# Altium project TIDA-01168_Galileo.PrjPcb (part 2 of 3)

## Sheet TIDA-01168_Control.SchDoc: System Control
size 431 x 279 mm; Date: Not shown in title block; ApprovedBy: Not shown in title block; CheckedBy: Not shown in title block; Author: Not shown in title block; CompanyName: Not shown in title block; Engineer: Not shown in title block; Organization: Not shown in title block; Address1: Not shown in title block; Address2: Not shown in title block; Address3: Not shown in title block; Address4: Not shown in title block; DocumentNumber: 8; Revision: Use project parameter SCH_Rev; SheetNumber: 8; SheetTotal: 11; PageSetup: Record=PageOptions¦CenterHorizontal=True¦CenterVertical=True¦PrintScale=1.00¦XCorrection=1.00¦YCorrection=1.00¦PrintKind=0¦BorderSize=5000000¦LeftOffset=0¦BottomOffset=0¦Orientation=2¦PaperLength=1000¦PaperWidth=1000¦Scale=100¦PaperSource=15¦PrintQuality=600¦MediaType=1¦DitherType=10¦PaperKind=Letter¦PrintScaleMode=1
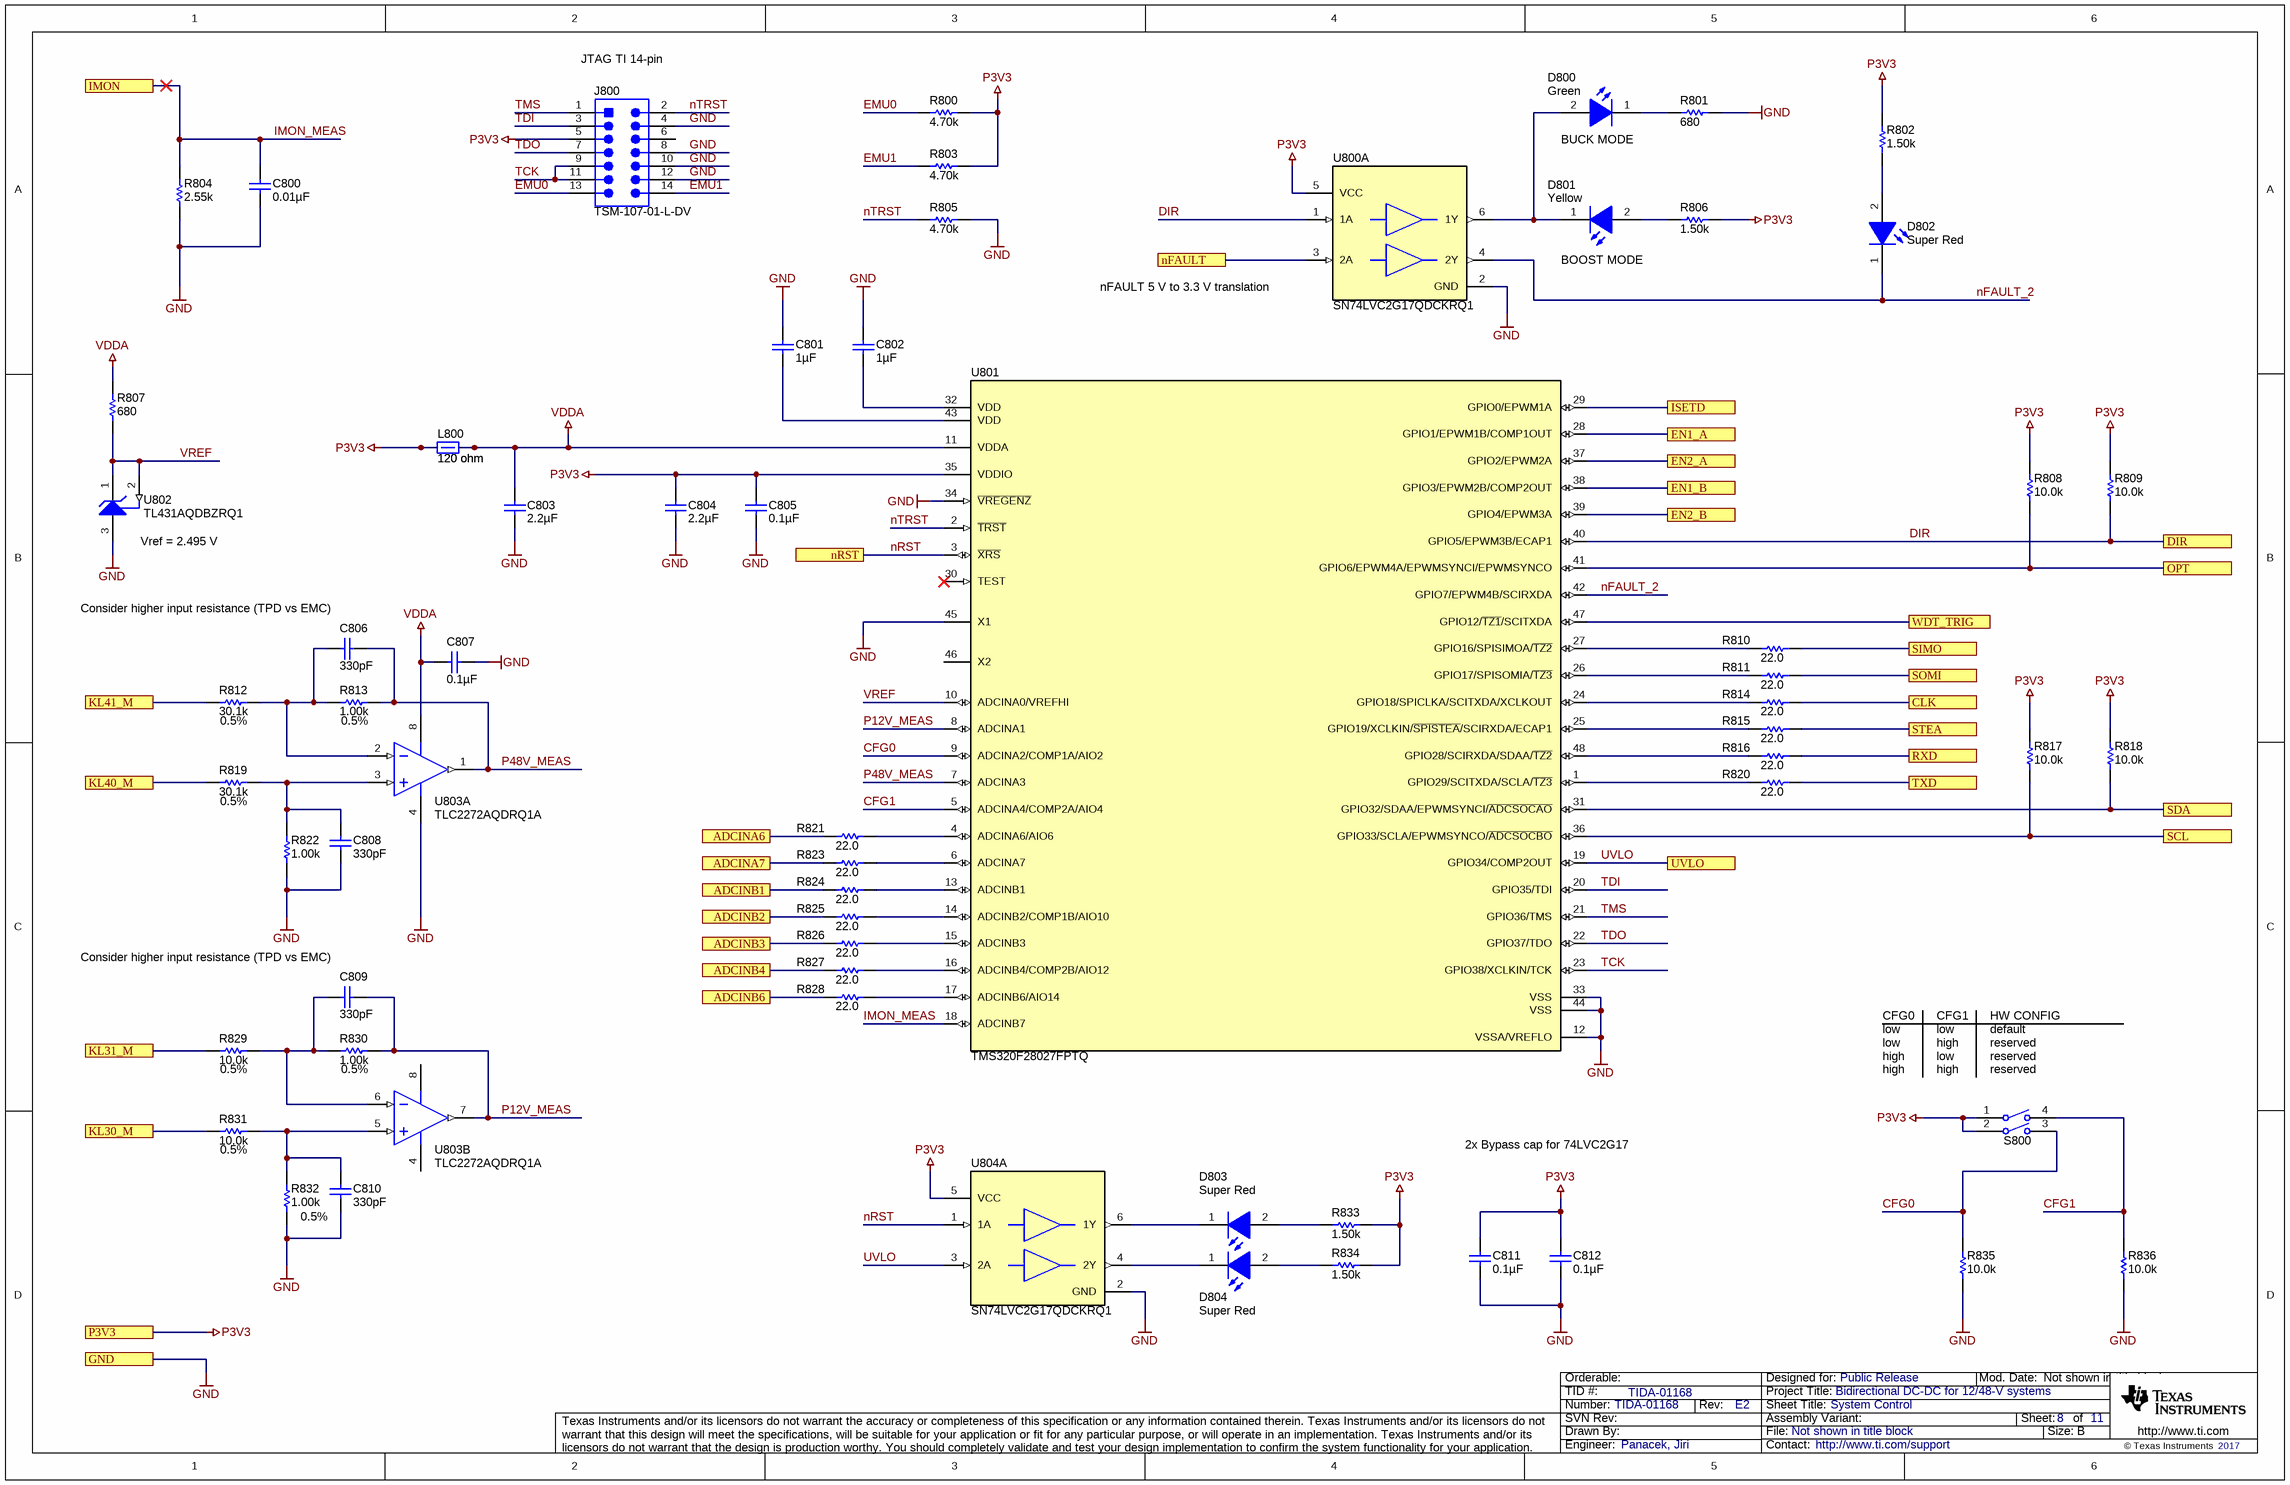
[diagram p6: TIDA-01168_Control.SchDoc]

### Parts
C800  ValueDisplayed: 0.01µF  [0603]  (hidden comment: GCM188R71H103KA37D)
C801  ValueDisplayed: 1µF  [0603]  (hidden comment: GCM188R71E105KA64D)
C802  ValueDisplayed: 1µF  [0603]  (hidden comment: GCM188R71E105KA64D)
C803  ValueDisplayed: 2.2µF  [0603]  (hidden comment: GCM188R70J225KE22D)
C804  ValueDisplayed: 2.2µF  [0603]  (hidden comment: GCM188R70J225KE22D)
C805  ValueDisplayed: 0.1µF  [0603]  (hidden comment: GCM188R71H104KA57D)
C806  ValueDisplayed: 330pF  [0603]  (hidden comment: C1608C0G2A331J080AA)
C807  ValueDisplayed: 0.1µF  [0603]  (hidden comment: GCM188R71H104KA57D)
C808  ValueDisplayed: 330pF  [0603]  (hidden comment: C1608C0G2A331J080AA)
C809  ValueDisplayed: 330pF  [0603]  (hidden comment: C1608C0G2A331J080AA)
C810  ValueDisplayed: 330pF  [0603]  (hidden comment: C1608C0G2A331J080AA)
C811  ValueDisplayed: 0.1µF  [0603]  (hidden comment: GCM188R71H104KA57D)
C812  ValueDisplayed: 0.1µF  [0603]  (hidden comment: GCM188R71H104KA57D)
D800  value Green  [WL-SMCW_GREEN]  (hidden comment: 150060GS75000)
D801  value Yellow  [WL-SMCW_YELLOW]  (hidden comment: 150060YS75000)
D802  value Super Red  [WL-SMCW_RED]  (hidden comment: 150060SS75000)
D803  value Super Red  [WL-SMCW_RED]  (hidden comment: 150060SS75000)
D804  value Super Red  [WL-SMCW_RED]  (hidden comment: 150060SS75000)
J800  TSM-107-01-L-DV  [Samtec_TSM-107-01-x-DV]
L800  value 120 ohm  [0603]  (hidden comment: BLM18AG121SN1D)
R800  ValueDisplayed: 4.70k  [0603]  (hidden comment: RC0603FR-074K7L)
R801  ValueDisplayed: 680  [0603]  (hidden comment: RC0603FR-07680RL)
R802  ValueDisplayed: 1.50k  [0603]  (hidden comment: RC0603FR-071K5L)
R803  ValueDisplayed: 4.70k  [0603]  (hidden comment: RC0603FR-074K7L)
R804  ValueDisplayed: 2.55k  [0603]  (hidden comment: RC0603FR-072K55L)
R805  ValueDisplayed: 4.70k  [0603]  (hidden comment: RC0603FR-074K7L)
R806  ValueDisplayed: 1.50k  [0603]  (hidden comment: RC0603FR-071K5L)
R807  ValueDisplayed: 680  [0603]  (hidden comment: RC0603FR-07680RL)
R808  ValueDisplayed: 10.0k  [0603]  (hidden comment: RC0603FR-0710KL)
R809  ValueDisplayed: 10.0k  [0603]  (hidden comment: RC0603FR-0710KL)
R810  ValueDisplayed: 22.0  [0603]  (hidden comment: RC0603FR-0722RL)
R811  ValueDisplayed: 22.0  [0603]  (hidden comment: RC0603FR-0722RL)
R812  ValueDisplayed: 30.1k  Value1: 0.5%  [0603]  (hidden comment: RT0603DRE0730K1L)
R813  ValueDisplayed: 1.00k  Value1: 0.5%  [0603]  (hidden comment: RT0603DRE071KL)
R814  ValueDisplayed: 22.0  [0603]  (hidden comment: RC0603FR-0722RL)
R815  ValueDisplayed: 22.0  [0603]  (hidden comment: RC0603FR-0722RL)
R816  ValueDisplayed: 22.0  [0603]  (hidden comment: RC0603FR-0722RL)
R817  ValueDisplayed: 10.0k  [0603]  (hidden comment: RC0603FR-0710KL)
R818  ValueDisplayed: 10.0k  [0603]  (hidden comment: RC0603FR-0710KL)
R819  ValueDisplayed: 30.1k  Value1: 0.5%  [0603]  (hidden comment: RT0603DRE0730K1L)
R820  ValueDisplayed: 22.0  [0603]  (hidden comment: RC0603FR-0722RL)
R821  ValueDisplayed: 22.0  [0603]  (hidden comment: RC0603FR-0722RL)
R822  ValueDisplayed: 1.00k  [0603]  (hidden comment: RT0603DRE071KL)
R823  ValueDisplayed: 22.0  [0603]  (hidden comment: RC0603FR-0722RL)
R824  ValueDisplayed: 22.0  [0603]  (hidden comment: RC0603FR-0722RL)
R825  ValueDisplayed: 22.0  [0603]  (hidden comment: RC0603FR-0722RL)
R826  ValueDisplayed: 22.0  [0603]  (hidden comment: RC0603FR-0722RL)
R827  ValueDisplayed: 22.0  [0603]  (hidden comment: RC0603FR-0722RL)
R828  ValueDisplayed: 22.0  [0603]  (hidden comment: RC0603FR-0722RL)
R829  ValueDisplayed: 10.0k  Value1: 0.5%  [0603]  (hidden comment: RT0603DRE0710KL)
R830  ValueDisplayed: 1.00k  Value1: 0.5%  [0603]  (hidden comment: RT0603DRE071KL)
R831  ValueDisplayed: 10.0k  Value1: 0.5%  [0603]  (hidden comment: RT0603DRE0710KL)
R832  ValueDisplayed: 1.00k  Value1: 0.5%  [0603]  (hidden comment: RT0603DRE071KL)
R833  ValueDisplayed: 1.50k  [0603]  (hidden comment: RC0603FR-071K5L)
R834  ValueDisplayed: 1.50k  [0603]  (hidden comment: RC0603FR-071K5L)
R835  ValueDisplayed: 10.0k  [0603]  (hidden comment: RC0603FR-0710KL)
R836  ValueDisplayed: 10.0k  [0603]  (hidden comment: RC0603FR-0710KL)
S800  218-2LPST  [SW_218-2LP]  (value not drawn)
U800  SN74LVC2G17QDCKRQ1  [DCK0006A_N]  (part A of 2)
U801  TMS320F28027FPTQ  [PT0048A_N]
U802  TL431AQDBZRQ1  [DBZ0003A_N]
U803  TLC2272AQDRQ1A  [D0008A_N]  (parts A,B of 2)
U804  SN74LVC2G17QDCKRQ1  [DCK0006A_N]  (part A of 2)

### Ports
ADCINA6, ADCINA7, ADCINB1, ADCINB2, ADCINB3, ADCINB4, ADCINB6, CLK, DIR, EN1_A, EN1_B, EN2_A, EN2_B, GND, IMON, ISETD, KL30_M, KL31_M, KL40_M, KL41_M, nFAULT, nRST, OPT, P3V3, RXD, SCL, SDA, SIMO, SOMI, STEA, TXD, UVLO, WDT_TRIG

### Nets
GND: C800.2 C801.2 C802.2 C803.1 C804.1 C805.1 C807.2 C808.2 C810.2 C811.2 C812.2 J800.4 J800.8 J800.10 J800.12 R801.2 R804.1 R805.1 R822.2 R832.2 R835.1 R836.1 U800.2(GND) U801.12(VSSA/VREFLO) U801.33(VSS) U801.34(~{VREGENZ}) U801.44(VSS) U801.45(X1) U802.3(ANODE) U803.4(VDD-/GND) U804.2(GND) ; port GND
P3V3: C804.2 C805.2 C811.1 C812.1 J800.5 L800.1 R800.1 R802.2 R803.1 R806.2 R808.2 R809.2 R817.2 R818.2 R833.2 R834.2 S800.1 S800.2 U800.5(VCC) U801.35(VDDIO) U804.5(VCC) ; port P3V3
VDDA: C803.2 C807.1 L800.2 R807.1 U801.11(VDDA) U803.8(VDD+)
ADCINA6: R821.2 ; port ADCINA6
ADCINA7: R823.2 ; port ADCINA7
ADCINB1: R824.2 ; port ADCINB1
ADCINB2: R825.2 ; port ADCINB2
ADCINB3: R826.2 ; port ADCINB3
ADCINB4: R827.2 ; port ADCINB4
ADCINB6: R828.2 ; port ADCINB6
CFG0: R835.2 S800.3 U801.9(ADCINA2/COMP1A/AIO2)
CFG1: R836.2 S800.4 U801.5(ADCINA4/COMP2A/AIO4)
CLK: R814.1 ; port CLK
DIR: R809.1 U800.1(1A) U801.40(GPIO5/EPWM3B/ECAP1) ; port DIR
EMU0: J800.13 R800.2
EMU1: J800.14 R803.2
EN1: U801.28(GPIO1/EPWM1B/COMP1OUT) ; port EN1_A
EN1: U801.38(GPIO3/EPWM2B/COMP2OUT) ; port EN1_B  [a separate net that carries the same name]
EN2: U801.37(GPIO2/EPWM2A) ; port EN2_A
EN2: U801.39(GPIO4/EPWM3A) ; port EN2_B  [a separate net that carries the same name]
IMON_MEAS: C800.1 R804.2 U801.18(ADCINB7) ; port IMON  [project net IMON]
ISETD: U801.29(GPIO0/EPWM1A) ; port ISETD
KL30_M: R831.2 ; port KL30_M
KL31_M: R829.2 ; port KL31_M
KL40_M: R819.2 ; port KL40_M
KL41_M: R812.2 ; port KL41_M
nFAULT: U800.3(2A) ; port nFAULT
nFAULT_2: D802.1(K) U800.4(2Y) U801.42(GPIO7/EPWM4B/SCIRXDA)
nRST: U801.3(~{XRS}) U804.1(1A) ; port nRST
nTRST: J800.2 R805.2 U801.2(~{TRST})
OPT: R808.1 U801.41(GPIO6/EPWM4A/EPWMSYNCI/EPWMSYNCO) ; port OPT
P12V_MEAS: C809.2 R830.1 U801.8(ADCINA1) U803.7(OUT2)
P48V_MEAS: C806.2 R813.1 U801.7(ADCINA3) U803.1(OUT1)
RXD: R816.1 ; port RXD
SCL: R817.1 U801.36(GPIO33/SCLA/EPWMSYNCO/~{ADCSOCBO}) ; port SCL
SDA: R818.1 U801.31(GPIO32/SDAA/EPWMSYNCI/~{ADCSOCAO}) ; port SDA
SIMO: R810.1 ; port SIMO
SOMI: R811.1 ; port SOMI
STEA: R815.1 ; port STEA
TCK: J800.9 J800.11 U801.23(GPIO38/XCLKIN/TCK)
TDI: J800.3 U801.20(GPIO35/TDI)
TDO: J800.7 U801.22(GPIO37/TDO)
TMS: J800.1 U801.21(GPIO36/TMS)
TXD: R820.1 ; port TXD
UVLO: U801.19(GPIO34/COMP2OUT) U804.3(2A) ; port UVLO
VREF: R807.2 U801.10(ADCINA0/VREFHI) U802.1(CATHODE) U802.2(REF)
WDT_TRIG: U801.47(GPIO12/~{TZ1}/SCITXDA) ; port WDT_TRIG
NetC801_1: C801.1 U801.43(VDD)
NetC802_1: C802.1 U801.32(VDD)
NetC806_1: C806.1 R812.1 R813.2 U803.2(IN1-)
NetC808_1: C808.1 R819.1 R822.1 U803.3(IN1+)
NetC809_1: C809.1 R829.1 R830.2 U803.6(IN2-)
NetC810_1: C810.1 R831.1 R832.1 U803.5(IN2+)
NetD800_1: D800.1(K) R801.1
NetD800_2: D800.2(A) D801.1(K) U800.6(1Y)
NetD801_2: D801.2(A) R806.1
NetD802_2: D802.2(A) R802.1
NetD803_1: D803.1(K) U804.6(1Y)
NetD803_2: D803.2(A) R833.1
NetD804_1: D804.1(K) U804.4(2Y)
NetD804_2: D804.2(A) R834.1
NetR810_2: R810.2 U801.27(GPIO16/SPISIMOA/~{TZ2})
NetR811_2: R811.2 U801.26(GPIO17/SPISOMIA/~{TZ3})
NetR814_2: R814.2 U801.24(GPIO18/SPICLKA/SCITXDA/XCLKOUT)
NetR815_2: R815.2 U801.25(GPIO19/XCLKIN/~{SPISTEA}/SCIRXDA/ECAP1)
NetR816_2: R816.2 U801.48(GPIO28/SCIRXDA/SDAA/~{TZ2})
NetR820_2: R820.2 U801.1(GPIO29/SCITXDA/SCLA/~{TZ3})
NetR821_1: R821.1 U801.4(ADCINA6/AIO6)
NetR823_1: R823.1 U801.6(ADCINA7)
NetR824_1: R824.1 U801.13(ADCINB1)
NetR825_1: R825.1 U801.14(ADCINB2/COMP1B/AIO10)
NetR826_1: R826.1 U801.15(ADCINB3)
NetR827_1: R827.1 U801.16(ADCINB4/COMP2B/AIO12)
NetR828_1: R828.1 U801.17(ADCINB6/AIO14)

Not connected (* = marked no-connect by the designer): J800 6; U801 30(TEST)* 46(X2)

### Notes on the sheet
- (near J800) JTAG TI 14-pin
- (near D800) BUCK MODE
- nFAULT 5 V to 3.3 V translation
- (near D801) BOOST MODE
- (near U802) Vref = 2.495 V
- (near C806) Consider higher input resistance (TPD vs EMC)
- (near C809) Consider higher input resistance (TPD vs EMC)
- CFG0
- low
- CFG1
- HW CONFIG
- default
- high
- reserved
- (near S800) reserved
- 2x Bypass cap for 74LVC2G17

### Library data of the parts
C800 = GCM188R71H103KA37D: CAP, CERM, 0.01 µF, 50 V, +/- 10%, X7R, AEC-Q200 Grade 1, 0603; Manufacturer: MuRata; Polarized: N; CompType: Capacitor; Value: 0.01uF; U/M: EA; Cap_F: 0.00000001; Tolerance_%: 10; Value1: Unknown; VDC_V: 50; Value2: 50V; TaMin_C: -55; TaMax_C: 125; SizeArea_mm2: 1.28; SizeAreaWB_mm2: 4.68; SizeX_mm: 1.6; SizeY_mm: 0.8; SizeZ_mm: 1; AEC Category: Q200; AEC Qualified: Y
C801 C802 = GCM188R71E105KA64D: CAP, CERM, 1 µF, 25 V, +/- 10%, X7R, AEC-Q200 Grade 1, 0603; Manufacturer: MuRata; Polarized: N; CompType: Capacitor; Value: 1uF; U/M: EA; Cap_F: 0.000001; Tolerance_%: 10; Value1: Unknown; VDC_V: 25; Value2: 25V; TaMin_C: -55; TaMax_C: 125; AEC Category: Q200; AEC Qualified: Y; AEC Grade: 1; SizeArea_mm2: 1.28; SizeAreaWB_mm2: 4.68; SizeX_mm: 1.6; SizeY_mm: 0.8
C803 C804 = GCM188R70J225KE22D: CAP, CERM, 2.2 µF, 6.3 V, +/- 10%, X7R, AEC-Q200 Grade 1, 0603; Manufacturer: MuRata; Polarized: N; CompType: Capacitor; Value: 2.2uF; U/M: EA; Cap_F: 0.0000022; Tolerance_%: 10; Value1: Unknown; VDC_V: 6.3; Value2: 6.3V; TaMin_C: -55; TaMax_C: 125; AEC Category: Q200; AEC Qualified: Y; AEC Grade: 1; SizeArea_mm2: 1.28; SizeAreaWB_mm2: 4.68; SizeX_mm: 1.6; SizeY_mm: 0.8
C805 C807 C811 C812 = GCM188R71H104KA57D: CAP, CERM, 0.1 µF, 50 V, +/- 10%, X7R, 0603; Manufacturer: MuRata; Polarized: N; CompType: Capacitor; Value: 0.1uF; U/M: EA; Cap_F: 0.0000001; Tolerance_%: 10; ESR_ohm: 0.02; Value1: 0.02 ohm; VDC_V: 50; Value2: 50V; IRMS_A: 1.84; TaMin_C: -55; TaMax_C: 125; SizeArea_mm2: 1.28; SizeAreaWB_mm2: 4.68; SizeX_mm: 1.6; SizeY_mm: 0.8; SizeZ_mm: 1; AEC Category: Q200
C806 C808-C810 = C1608C0G2A331J080AA: CAP, CERM, 330 pF, 100 V, +/- 5%, C0G/NP0, 0603; Manufacturer: TDK; Polarized: N; CompType: Capacitor; Value: 330pF; U/M: EA; Cap_F: 0.00000000033; Tolerance_%: 5; ESR_ohm: 0.1269; Value1: 0.1269 ohm; VDC_V: 100; Value2: 100V; TaMin_C: -55; TaMax_C: 125; SizeArea_mm2: 1.28; SizeAreaWB_mm2: 4.68; SizeX_mm: 1.6; SizeY_mm: 0.8; SizeZ_mm: 1; AEC Category: Q200
D800 = 150060GS75000: LED, Green, SMD; Manufacturer: Wurth Elektronik; Type: InGaN; Vf_V: 3.2; Value2: 3.2V; Io_A: 0.02; Tjmax_C: 85; Value1: W; Angle: 140; U/M: EA
D801 = 150060YS75000: LED, Yellow, SMD; Manufacturer: Wurth Elektronik; Type: AlInGaP; Vf_V: 2; Value2: 2V; Io_A: 0.02; Value1: W; U/M: EA
D802-D804 = 150060SS75000: LED, Super Red, SMD; Manufacturer: Wurth Elektronik; Type: AlInGaP; Vf_V: 1.9; Value2: 1.9V; Io_A: 0.02; Value1: W; U/M: EA
J800 = TSM-107-01-L-DV: Header, 2.54mm, 7x2, Gold, SMT; Manufacturer: Samtec; SymbolCreator: a0412235; Pitch_mm: 2.54; Gender: Male; Shrouded: N; Row_Count: 2; Current_A: 5.4; Cert_CSA: Y
L800 = BLM18AG121SN1D: Ferrite Bead, 120 ohm @ 100 MHz, 0.5 A, 0603; Manufacturer: MuRata; Imax_A: 0.5; DCR_ohm: 0.18; Value1: 0.18 ohm; Value2: 0.5A; ZTyp@100MHz_Ohm: 120; SizeAreaWB_mm2: 4.68; SizeArea_mm2: 1.28; SizeX_mm: 1.6; SizeY_mm: 0.8; SizeZ_mm: 1
R800 R803 R805 = RC0603FR-074K7L: RES, 4.70 k, 1%, 0.1 W, 0603; Manufacturer: Yageo America; CompType: Resistor; Value: 4.70k; Res_ohm: 4700; Value_Code: 4k70; Tolerance_%: 1; Power_W: 0.1; Value2: 0.1W; VDC_V: 150; TempCo: 200 ppm/C; U/M: EA; AEC Category: Q200; SizeArea_mm2: 1.28; SizeX_mm: 1.6; SizeY_mm: 0.8
R801 R807 = RC0603FR-07680RL: RES, 680, 1%, 0.1 W, 0603; Manufacturer: Yageo America; CompType: Resistor; Value: 680; Value_Code: 680R; Tolerance_%: 1; Power_W: 0.1; Value2: 0.1W; VDC_V: 150; TempCo: 200 ppm/C; U/M: EA; AEC Category: Q200; SizeArea_mm2: 1.28; SizeX_mm: 1.6; SizeY_mm: 0.8
R802 R806 R833 R834 = RC0603FR-071K5L: RES, 1.50 k, 1%, 0.1 W, 0603; Manufacturer: Yageo America; CompType: Resistor; Value: 1.50k; Res_ohm: 1500; Value_Code: 1k50; Tolerance_%: 1; Power_W: 0.1; Value2: 0.1W; VDC_V: 150; TempCo: 200 ppm/C; EIA_Code: E96; U/M: EA; AEC Category: Q200; SizeArea_mm2: 1.28; SizeX_mm: 1.6; SizeY_mm: 0.8
R804 = RC0603FR-072K55L: RES, 2.55 k, 1%, 0.1 W, 0603; Manufacturer: Yageo America; CompType: Resistor; Value: 2.55k; Res_ohm: 2550; Value_Code: 2k55; Tolerance_%: 1; Power_W: 0.1; Value2: 0.1W; VDC_V: 150; TempCo: 200 ppm/C; EIA_Code: E96; U/M: EA; AEC Category: Q200; SizeArea_mm2: 1.28; SizeX_mm: 1.6; SizeY_mm: 0.8
R808 R809 R817 R818 R835 R836 = RC0603FR-0710KL: RES, 10.0 k, 1%, 0.1 W, 0603; Manufacturer: Yageo America; CompType: Resistor; Value: 10.0k; Res_ohm: 10000; Value_Code: 10k0; Tolerance_%: 1; Power_W: 0.1; Value2: 0.1W; VDC_V: 150; TempCo: 200 ppm/C; EIA_Code: E96; U/M: EA; AEC Category: Q200; SizeArea_mm2: 1.28; SizeX_mm: 1.6; SizeY_mm: 0.8
R810 R811 R814-R816 R820 R821 R823-R828 = RC0603FR-0722RL: RES, 22.0, 1%, 0.1 W, 0603; Manufacturer: Yageo America; CompType: Resistor; Value: 22.0; Res_ohm: 22; Value_Code: 22R0; Tolerance_%: 1; Power_W: 0.1; Value2: 0.1W; VDC_V: 150; TempCo: 200 ppm/C; U/M: EA; AEC Category: Q200; SizeArea_mm2: 1.28; SizeX_mm: 1.6; SizeY_mm: 0.8
R812 R819 = RT0603DRE0730K1L: RES, 30.1 k, 0.5%, 0.1 W, 0603; Manufacturer: Yageo America; CompType: Resistor; Value: 30.1k; Res_ohm: 30100; Value_Code: 30k1; Tolerance_%: 0.5; Power_W: 0.1; Value2: 0.1W; VDC_V: 75; TempCo: 50 ppm/C; EIA_Code: E192; U/M: EA; AEC Category: Q200; SizeArea_mm2: 1.28; SizeX_mm: 1.6; SizeY_mm: 0.8; SizeZ_mm: 1
R813 R822 R830 R832 = RT0603DRE071KL: RES, 1.00 k, 0.5%, 0.1 W, 0603; Manufacturer: Yageo America; CompType: Resistor; Value: 1.00k; Res_ohm: 1000; Value_Code: 1k00; Tolerance_%: 0.5; Power_W: 0.1; Value2: 0.1W; VDC_V: 75; TempCo: 50 ppm/C; EIA_Code: E192; U/M: EA; AEC Category: Q200; SizeArea_mm2: 1.28; SizeX_mm: 1.6; SizeY_mm: 0.8; SizeZ_mm: 1
R829 R831 = RT0603DRE0710KL: RES, 10.0 k, 0.5%, 0.1 W, 0603; Manufacturer: Yageo America; CompType: Resistor; Value: 10.0k; Res_ohm: 10000; Value_Code: 10k0; Tolerance_%: 0.5; Power_W: 0.1; Value2: 0.1W; VDC_V: 75; TempCo: 50 ppm/C; EIA_Code: E192; U/M: EA; AEC Category: Q200; SizeArea_mm2: 1.28; SizeX_mm: 1.6; SizeY_mm: 0.8; SizeZ_mm: 1
S800 = 218-2LPST: Switch, SPST, 2 Pos, 25mA, 24VDC, SMD; Manufacturer: CTS Electrocomponents; SymbolCreator: Altium; VDC_V: 24; SwitchFunction: Off-On; PositionCount: 2; CurrentRating_mA: 25
U800 U804 = SN74LVC2G17QDCKRQ1: Dual Schmitt Trigger Buffer, DCK0006A (SOT-6); Manufacturer: Texas Instruments; SymbolCreator: Altium; SizeArea_mm2: 4.2; SizeAreaWB_mm2: 9.3; SizeX_mm: 2.1; SizeY_mm: 2; SizeZ_mm: 1.1; CompType: IC; U/M: EA
U801 = TMS320F28027FPTQ: Piccolo Microcontroller, PT0048A (LQFP-48); Alternate PartNumber: TMS320F28027FPTT; Manufacturer: Texas Instruments; SymbolCreator: Altium; SizeArea_mm2: 81; SizeAreaWB_mm2: 121; SizeX_mm: 9; SizeZ_mm: 1.6; CompType: IC; U/M: EA
U802 = TL431AQDBZRQ1: Automotive Catalog Adjustable Precision Shunt Regulator, 34 ppm / degC, 100 mA, -40 to 125 degC, 3-pin SOT-23 (DBZ), Green (RoHS & no Sb/Br); Manufacturer: Texas Instruments; Alternate PartNumber: Equivalent; Initial Accuracy @ 25/deg C(%): 1; Iout/Iz(Max)(mA): 100; Min Iz for Regulation(uA): 600; SubFamily: Shunt Voltage Reference; Temp Coeff(Typ)(ppm/ degree C): 34; VO Adj(Max)(V): 36; VO Adj(Min)(V): 2.495
U803 = TLC2272AQDRQ1: Automotive Catalog Advanced LinCMOS(TM) Rail-to-Rail Operational Amplifier, 4.4 to 16 V, -40 to 125 degC, 8-pin SOIC (D0008A), Green (RoHS & no Sb/Br); Manufacturer: Texas Instruments; Alternate PartNumber: Equivalent; CMRR(Min)(dB): 70; IIB(Max)(pA): 60; Iq per channel(Max)(mA): 1.5; Number of Channels: 2; Slew Rate(Typ)(V/us): 3.6; Sub Family: Low Noise Amp (<=10nV/rtHz), Precision Amplifier; Total Supply Voltage(Max)(+5V is 5, +/-5V is 10): 16; Total Supply Voltage(Min)(+5V is 5, +/-5V is 10): 4.4; Vio (25C)(Max)(mV): 0.95; GBW(Typ)(MHz): 2.18; Packing: LARGE T&R

## Sheet TIDA-01168_LM5170_Subsystem.SchDoc: LM5170 Subsystem
size 431 x 279 mm; Date: Not shown in title block; ApprovedBy: Not shown in title block; CheckedBy: Not shown in title block; Author: Not shown in title block; CompanyName: Not shown in title block; Engineer: Not shown in title block; Organization: Not shown in title block; Address1: Not shown in title block; Address2: Not shown in title block; Address3: Not shown in title block; Address4: Not shown in title block; DocumentNumber: 6; Revision: Use project parameter SCH_Rev; SheetNumber: 6; SheetTotal: 11; PageSetup: Record=PageOptions¦CenterHorizontal=True¦CenterVertical=True¦PrintScale=1.00¦XCorrection=1.00¦YCorrection=1.00¦PrintKind=0¦BorderSize=5000000¦LeftOffset=0¦BottomOffset=0¦Orientation=2¦PaperLength=1000¦PaperWidth=1000¦Scale=100¦PaperSource=15¦PrintQuality=600¦MediaType=1¦DitherType=10¦PaperKind=Letter¦PrintScaleMode=1
Used 2 times, as channels LM, LM. Parts and nets are listed once, with the designators drawn on the sheet.
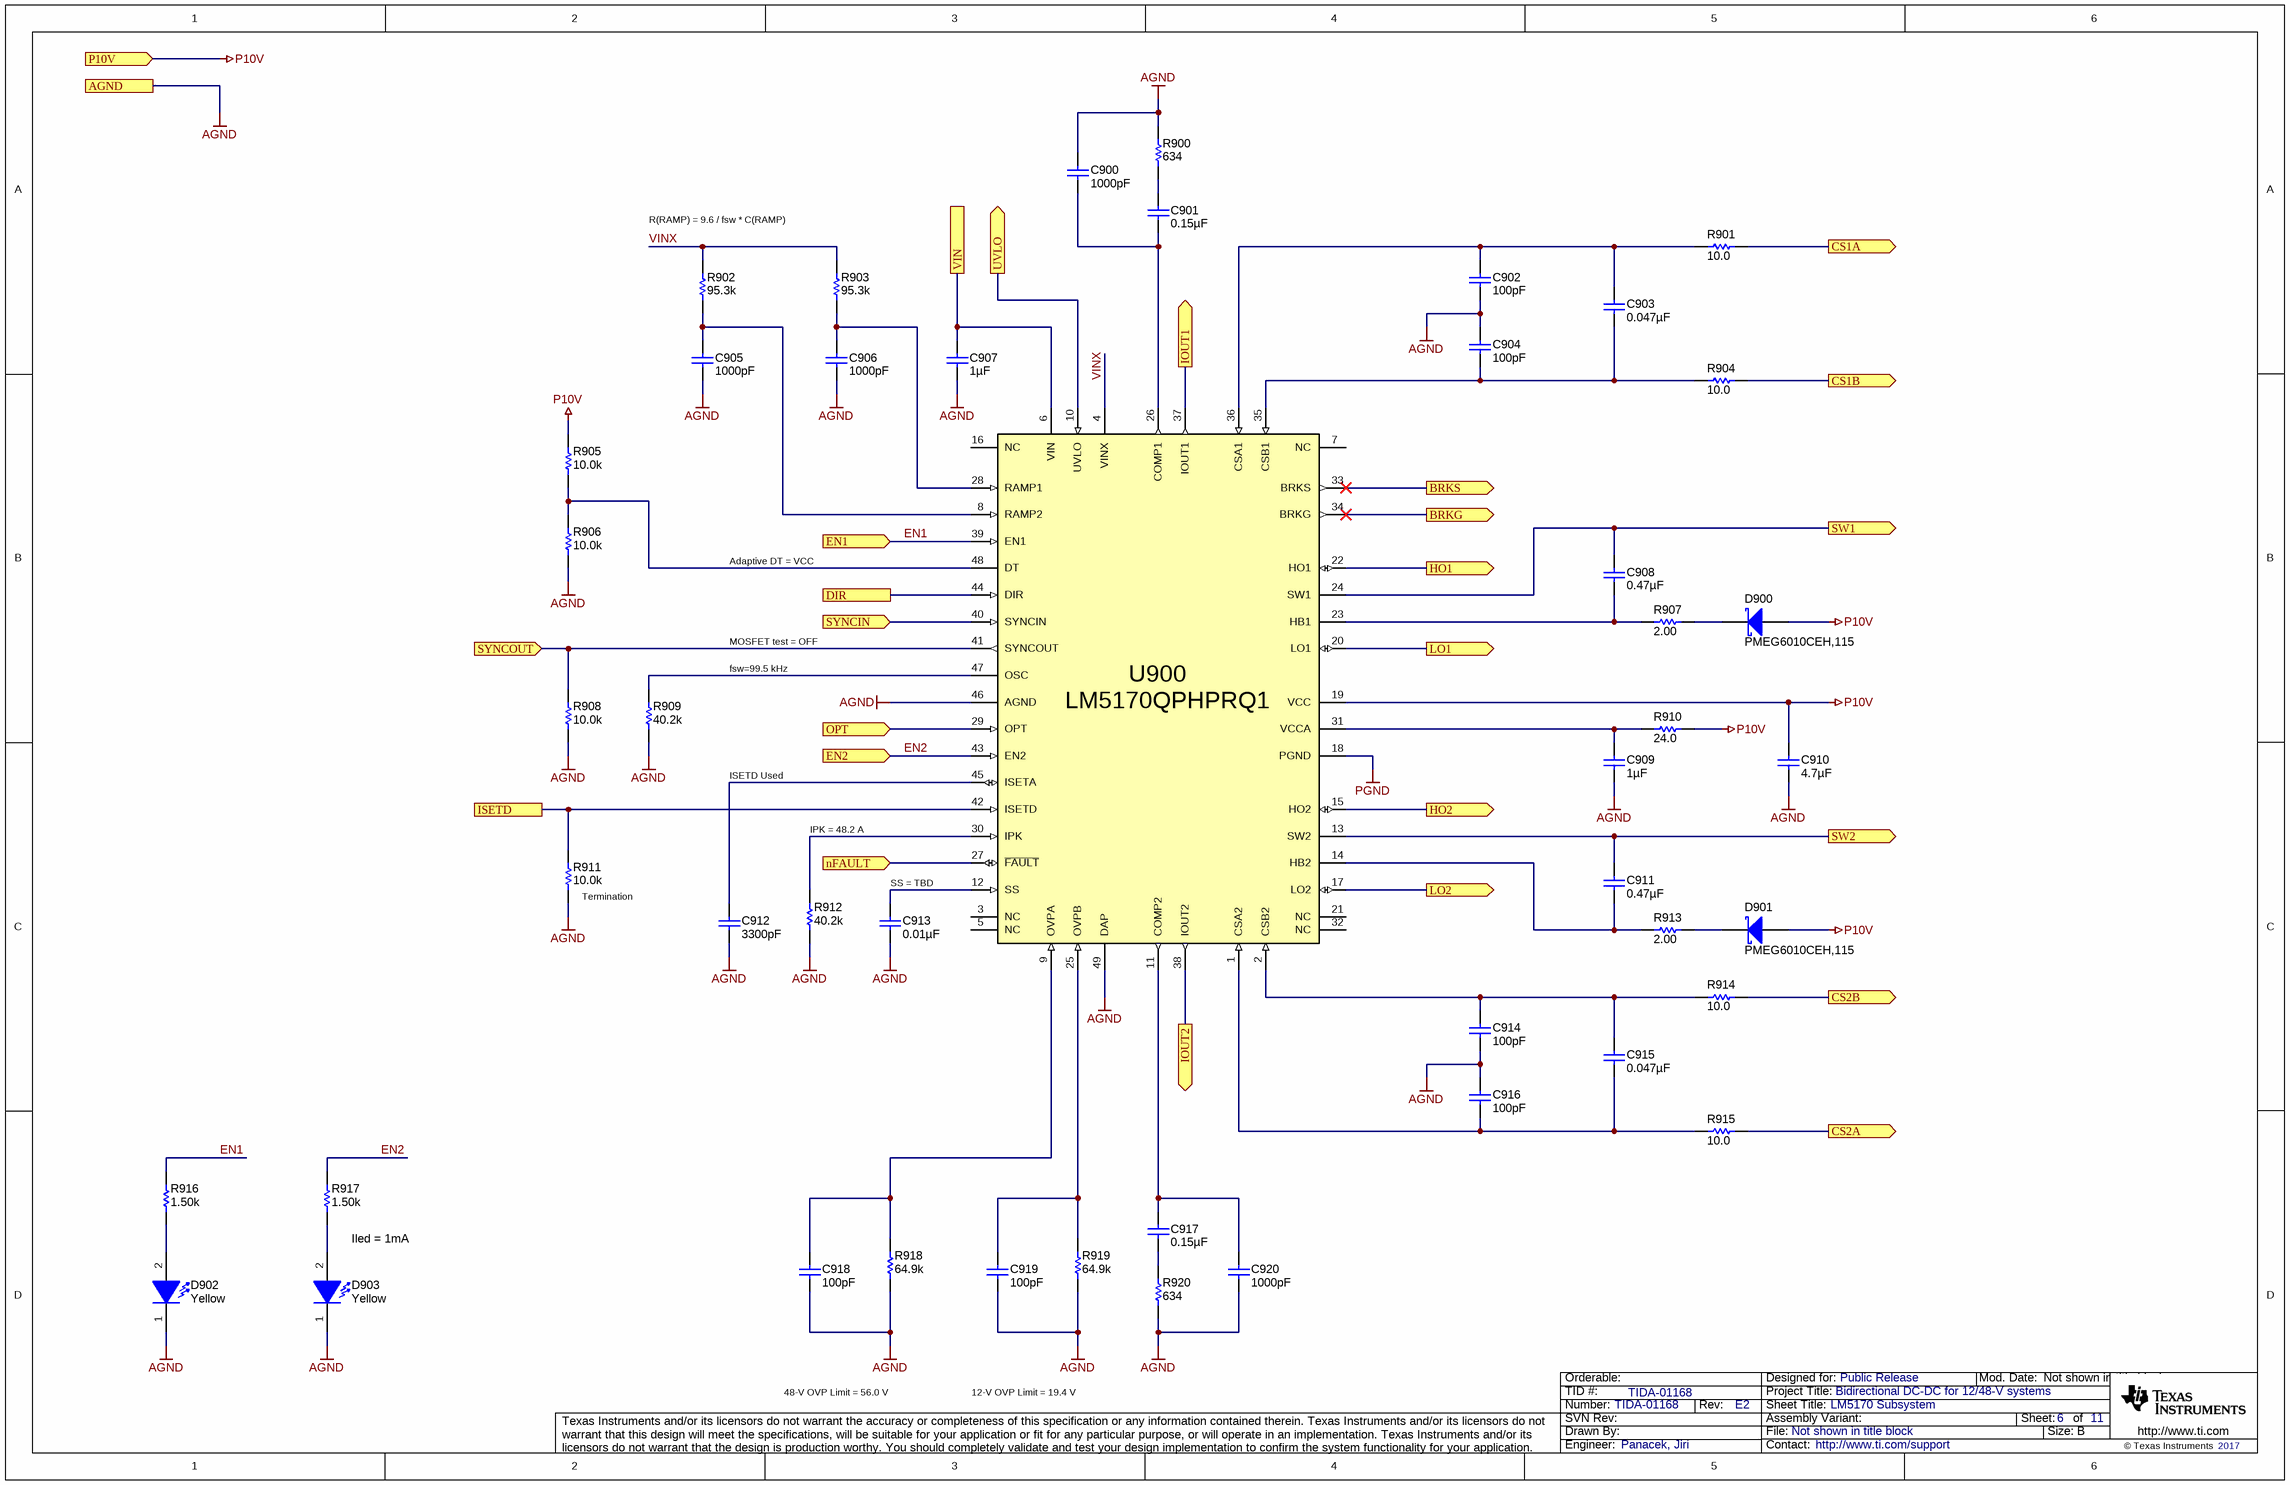
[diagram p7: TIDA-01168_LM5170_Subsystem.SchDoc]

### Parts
C900  ValueDisplayed: 1000pF  [0603]  (hidden comment: GCM1885C2A102JA16D)
C901  ValueDisplayed: 0.15µF  [0603]  (hidden comment: GRM188R71E154KA01D)
C902  ValueDisplayed: 100pF  [0603]  (hidden comment: GCM1885C2A101JA16D)
C903  ValueDisplayed: 0.047µF  [0603]  (hidden comment: GCM188R71E473KA37D)
C904  ValueDisplayed: 100pF  [0603]  (hidden comment: GCM1885C2A101JA16D)
C905  ValueDisplayed: 1000pF  [0603]  (hidden comment: GCM1885C2A102JA16D)
C906  ValueDisplayed: 1000pF  [0603]  (hidden comment: GCM1885C2A102JA16D)
C907  ValueDisplayed: 1µF  [1206_180]  (hidden comment: GRM31CR72A105KA01L)
C908  ValueDisplayed: 0.47µF  [0603]  (hidden comment: GCM188R71E474KA64D)
C909  ValueDisplayed: 1µF  [0603]  (hidden comment: GCM188R71E105KA64D)
C910  ValueDisplayed: 4.7µF  [0805_HV]  (hidden comment: GCM21BR71C475KA73K)
C911  ValueDisplayed: 0.47µF  [0603]  (hidden comment: GCM188R71E474KA64D)
C912  ValueDisplayed: 3300pF  [0603]  (hidden comment: GCM188R72A332KA37D)
C913  ValueDisplayed: 0.01µF  [0603]  (hidden comment: GCM188R71H103KA37D)
C914  ValueDisplayed: 100pF  [0603]  (hidden comment: GCM1885C2A101JA16D)
C915  ValueDisplayed: 0.047µF  [0603]  (hidden comment: GCM188R71E473KA37D)
C916  ValueDisplayed: 100pF  [0603]  (hidden comment: GCM1885C2A101JA16D)
C917  ValueDisplayed: 0.15µF  [0603]  (hidden comment: GRM188R71E154KA01D)
C918  ValueDisplayed: 100pF  [0603]  (hidden comment: GCM1885C2A101JA16D)
C919  ValueDisplayed: 100pF  [0603]  (hidden comment: GCM1885C2A101JA16D)
C920  ValueDisplayed: 1000pF  [0603]  (hidden comment: GCM1885C2A102JA16D)
D900  PMEG6010CEH,115  [SOD-123F]
D901  PMEG6010CEH,115  [SOD-123F]
D902  value Yellow  [WL-SMCW_YELLOW]  (hidden comment: 150060YS75000)
D903  value Yellow  [WL-SMCW_YELLOW]  (hidden comment: 150060YS75000)
R900  ValueDisplayed: 634  [0603]  (hidden comment: RC0603FR-07634RL)
R901  ValueDisplayed: 10.0  [0603]  (hidden comment: RC0603FR-0710RL)
R902  ValueDisplayed: 95.3k  [0603]  (hidden comment: RC0603FR-0795K3L)
R903  ValueDisplayed: 95.3k  [0603]  (hidden comment: RC0603FR-0795K3L)
R904  ValueDisplayed: 10.0  [0603]  (hidden comment: RC0603FR-0710RL)
R905  ValueDisplayed: 10.0k  [0603]  (hidden comment: RC0603FR-0710KL)
R906  ValueDisplayed: 10.0k  [0603]  (hidden comment: RC0603FR-0710KL)
R907  ValueDisplayed: 2.00  [0603]  (hidden comment: RC0603FR-072RL)
R908  ValueDisplayed: 10.0k  [0603]  (hidden comment: RC0603FR-0710KL)
R909  ValueDisplayed: 40.2k  [0603]  (hidden comment: RC0603FR-0740K2L)
R910  ValueDisplayed: 24.0  [0603]  (hidden comment: RC0603FR-0724RL)
R911  ValueDisplayed: 10.0k  [0603]  (hidden comment: RC0603FR-0710KL)
R912  ValueDisplayed: 40.2k  [0603]  (hidden comment: RC0603FR-0740K2L)
R913  ValueDisplayed: 2.00  [0603]  (hidden comment: RC0603FR-072RL)
R914  ValueDisplayed: 10.0  [0603]  (hidden comment: RC0603FR-0710RL)
R915  ValueDisplayed: 10.0  [0603]  (hidden comment: RC0603FR-0710RL)
R916  ValueDisplayed: 1.50k  [0603]  (hidden comment: RC0603FR-071K5L)
R917  ValueDisplayed: 1.50k  [0603]  (hidden comment: RC0603FR-071K5L)
R918  ValueDisplayed: 64.9k  [0603]  (hidden comment: RC0603FR-0764K9L)
R919  ValueDisplayed: 64.9k  [0603]  (hidden comment: RC0603FR-0764K9L)
R920  ValueDisplayed: 634  [0603]  (hidden comment: RC0603FR-07634RL)
U900  LM5170QPHPRQ1  [PHP0048D_N]

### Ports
AGND, BRKG, BRKS, CS1A, CS1B, CS2A, CS2B, DIR, EN1, EN2, HO1, HO2, IOUT1, IOUT2, ISETD, LO1, LO2, nFAULT, OPT, P10V, SW1, SW2, SYNCIN, SYNCOUT, UVLO, VIN

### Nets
AGND: C900.1 C902.2 C904.1 C905.2 C906.2 C907.2 C909.2 C910.2 C912.2 C913.2 C914.2 C916.1 C918.2 C919.2 C920.2 D902.1(K) D903.1(K) R900.2 R906.1 R908.1 R909.1 R911.1 R912.1 R918.1 R919.1 R920.1 U900.46(AGND) U900.49(DAP) ; port AGND
P10V: C910.1 D900.2(A) D901.2(A) R905.2 R910.2 U900.19(VCC) ; port P10V
PGND: U900.18(PGND)
BRKG: U900.34(BRKG) ; port BRKG
BRKS: U900.33(BRKS) ; port BRKS
CS1A: R901.2 ; port CS1A
CS1B: R904.2 ; port CS1B
CS2A: R915.2 ; port CS2A
CS2B: R914.2 ; port CS2B
DIR: U900.44(DIR) ; port DIR
EN1: R916.1 U900.39(EN1) ; port EN1
EN2: R917.1 U900.43(EN2) ; port EN2
HO1: U900.22(HO1) ; port HO1
HO2: U900.15(HO2) ; port HO2
IOUT1: U900.37(IOUT1) ; port IOUT1
IOUT2: U900.38(IOUT2) ; port IOUT2
ISETD: R911.2 U900.42(ISETD) ; port ISETD
LO1: U900.20(LO1) ; port LO1
LO2: U900.17(LO2) ; port LO2
nFAULT: U900.27(~{FAULT}) ; port nFAULT
OPT: U900.29(OPT) ; port OPT
SW1: C908.1 U900.24(SW1) ; port SW1
SW2: C911.1 U900.13(SW2) ; port SW2
SYNCIN: U900.40(SYNCIN) ; port SYNCIN
SYNCOUT: R908.2 U900.41(SYNCOUT) ; port SYNCOUT
UVLO: U900.10(UVLO) ; port UVLO
VIN: C907.1 U900.6(VIN) ; port VIN
VINX: R902.2 R903.2 U900.4(VINX)
NetC900_2: C900.2 C901.2 U900.26(COMP1)
NetC901_1: C901.1 R900.1
NetC902_1: C902.1 C903.1 R901.1 U900.36(CSA1)
NetC903_2: C903.2 C904.2 R904.1 U900.35(CSB1)
NetC905_1: C905.1 R902.1 U900.8(RAMP2)
NetC906_1: C906.1 R903.1 U900.28(RAMP1)
NetC908_2: C908.2 R907.1 U900.23(HB1)
NetC909_1: C909.1 R910.1 U900.31(VCCA)
NetC911_2: C911.2 R913.1 U900.14(HB2)
NetC912_1: C912.1 U900.45(ISETA)
NetC913_1: C913.1 U900.12(SS)
NetC914_1: C914.1 C915.1 R914.1 U900.2(CSB2)
NetC915_2: C915.2 C916.2 R915.1 U900.1(CSA2)
NetC917_1: C917.1 C920.1 U900.11(COMP2)
NetC917_2: C917.2 R920.2
NetC918_1: C918.1 R918.2 U900.9(OVPA)
NetC919_1: C919.1 R919.2 U900.25(OVPB)
NetD900_1: D900.1(K) R907.2
NetD901_1: D901.1(K) R913.2
NetD902_2: D902.2(A) R916.2
NetD903_2: D903.2(A) R917.2
NetR905_1: R905.1 R906.2 U900.48(DT)
NetR909_2: R909.2 U900.47(OSC)
NetR912_2: R912.2 U900.30(IPK)

Not connected (* = marked no-connect by the designer): U900 3(NC) 5(NC) 7(NC) 16(NC) 21(NC) 32(NC)

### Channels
LM: designators end in _LM2; ports AGND=GND BRKG=BRKG BRKS=BRKS CS1A=CS1A_A CS1B=CS1B_A CS2A=CS2A_A CS2B=CS1B_A DIR=DIR EN1=EN1 EN2=EN2 HO1=HO1_A HO2=HO2_A IOUT1=IMON IOUT2=IMON ISETD=ISETD LO1=LO1_A LO2=LO2_A nFAULT=nFAULT OPT=OPT P10V=P10V SW1=SW1_A SW2=SW2_A SYNCIN=SYNCIN_A SYNCOUT=SYNCOUT_A UVLO=UVLO VIN=VIN_LM
LM: designators end in _LM1; ports AGND=GND BRKG=BRKG BRKS=BRKS CS1A=CS1A_B CS1B=CS1B_A CS2A=CS2A_B CS2B=CS1B_A DIR=DIR EN1=EN1 EN2=EN2 HO1=HO1_B HO2=HO2_B IOUT1=IMON IOUT2=IMON ISETD=ISETD LO1=LO1_B LO2=LO2_B nFAULT=nFAULT OPT=OPT P10V=P10V SW1=SW1_B SW2=SW2_B SYNCIN=SYNCIN_B SYNCOUT=SYNCOUT_B UVLO=UVLO VIN=VIN_LM

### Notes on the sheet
- R(RAMP) = 9.6 / fsw * C(RAMP)
- Adaptive DT = VCC
- MOSFET test = OFF
- fsw=99.5 kHz
- ISETD Used
- IPK = 48.2 A
- (near R911) Termination
- (near C913) SS = TBD
- Iled = 1mA
- 48-V OVP Limit = 56.0 V
- 12-V OVP Limit = 19.4 V

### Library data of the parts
C900 C905 C906 C920 = GCM1885C2A102JA16D: CAP, CERM, 1000 pF, 100 V, +/- 5%, C0G/NP0, AEC-Q200 Grade 1, 0603; Manufacturer: MuRata; Polarized: N; CompType: Capacitor; Value: 1000pF; U/M: EA; Cap_F: 0.000000001; Tolerance_%: 5; Value1: Unknown; VDC_V: 100; Value2: 100V; TaMin_C: -55; TaMax_C: 125; SizeArea_mm2: 1.28; SizeAreaWB_mm2: 4.68; SizeX_mm: 1.6; SizeY_mm: 0.8; SizeZ_mm: 1; AEC Category: Q200; AEC Qualified: Y
C901 C917 = GRM188R71E154KA01D: CAP, CERM, 0.15 µF, 25 V, +/- 10%, X7R, 0603; Manufacturer: MuRata; Polarized: N; CompType: Capacitor; Value: 0.15uF; U/M: EA; Cap_F: 0.00000015; Tolerance_%: 10; Value1: Unknown; VDC_V: 25; Value2: 25V; TaMin_C: -55; TaMax_C: 125; SizeArea_mm2: 1.28; SizeAreaWB_mm2: 4.68; SizeX_mm: 1.6; SizeY_mm: 0.8; SizeZ_mm: 1; AEC Category: Q200
C902 C904 C914 C916 C918 C919 = GCM1885C2A101JA16D: CAP, CERM, 100 pF, 100 V, +/- 5%, C0G/NP0, AEC-Q200 Grade 1, 0603; Manufacturer: MuRata; Polarized: N; CompType: Capacitor; Value: 100pF; U/M: EA; Cap_F: 0.0000000001; Tolerance_%: 5; Value1: Unknown; VDC_V: 100; Value2: 100V; TaMin_C: -55; TaMax_C: 125; SizeArea_mm2: 1.28; SizeAreaWB_mm2: 4.68; SizeX_mm: 1.6; SizeY_mm: 0.8; SizeZ_mm: 1; AEC Category: Q200; AEC Qualified: Y
C903 C915 = GCM188R71E473KA37D: CAP, CERM, 0.047 µF, 25 V, +/- 10%, X7R, AEC-Q200 Grade 1, 0603; Manufacturer: MuRata; Polarized: N; CompType: Capacitor; Value: 0.047uF; U/M: EA; Cap_F: 0.000000047; Tolerance_%: 10; Value1: Unknown; VDC_V: 25; Value2: 25V; TaMin_C: -55; TaMax_C: 125; AEC Category: Q200; AEC Qualified: Y; AEC Grade: 1; SizeArea_mm2: 1.28; SizeAreaWB_mm2: 4.68; SizeX_mm: 1.6; SizeY_mm: 0.8
C907 = GRM31CR72A105KA01L: CAP, CERM, 1 µF, 100 V, +/- 10%, X7R, 1206; Manufacturer: MuRata; Polarized: N; CompType: Capacitor; Value: 1uF; U/M: EA; Cap_F: 0.000001; Tolerance_%: 10; Value1: Unknown; VDC_V: 100; Value2: 100V; TaMin_C: -55; TaMax_C: 125; Cap_Case: 2220; AEC Category: Q200; SizeArea_mm2: 5.12; SizeAreaWB_mm2: 10.92; SizeX_mm: 3.2; SizeY_mm: 1.6; SizeZ_mm: 1.8
C908 C911 = GCM188R71E474KA64D: CAP, CERM, 0.47 µF, 25 V, +/- 10%, X7R, AEC-Q200 Grade 1, 0603; Manufacturer: MuRata; Polarized: N; CompType: Capacitor; Value: 0.47uF; U/M: EA; Cap_F: 0.00000047; Tolerance_%: 10; Value1: Unknown; VDC_V: 25; Value2: 25V; TaMin_C: -55; TaMax_C: 125; AEC Category: Q200; AEC Qualified: Y; AEC Grade: 1; SizeArea_mm2: 1.28; SizeAreaWB_mm2: 4.68; SizeX_mm: 1.6; SizeY_mm: 0.8
C909 = GCM188R71E105KA64D: as C801 on sheet TIDA-01168_Control
C910 = GCM21BR71C475KA73K: CAP, CERM, 4.7 µF, 16 V, +/- 10%, X7R, AEC-Q200 Grade 1, 0805; Manufacturer: MuRata; Polarized: N; CompType: Capacitor; Value: 4.7uF; U/M: EA; Cap_F: 0.0000047; Tolerance_%: 10; Value1: Unknown; VDC_V: 16; Value2: 16V; TaMin_C: -55; TaMax_C: 125; Cap_Case: 0805; AEC Category: Q200; AEC Qualified: Y; AEC Grade: 1; SizeArea_mm2: 2.5; SizeAreaWB_mm2: 6.75; SizeX_mm: 2; SizeY_mm: 1.25; SizeZ_mm: 1.45
C912 = GCM188R72A332KA37D: CAP, CERM, 3300 pF, 100 V, +/- 10%, X7R, AEC-Q200 Grade 1, 0603; Manufacturer: MuRata; Polarized: N; CompType: Capacitor; Value: 3300pF; U/M: EA; Cap_F: 0.0000000033; Tolerance_%: 10; Value1: Unknown; VDC_V: 100; Value2: 100V; TaMin_C: -55; TaMax_C: 125; SizeArea_mm2: 1.28; SizeAreaWB_mm2: 4.68; SizeX_mm: 1.6; SizeY_mm: 0.8; SizeZ_mm: 1; AEC Category: Q200; AEC Qualified: Y
C913 = GCM188R71H103KA37D: as C800 on sheet TIDA-01168_Control
D900 D901 = PMEG6010CEH,115: Diode, Schottky, 60 V, 1 A, SOD-123F; Manufacturer: NXP Semiconductor; U/M: EA; Vf_V: 0.57; Value: 60V; Value1: 1A; Value2: 0.57V; Io_A: 1; Vr_V: 60; TJmax_C: 150; SizeAreaWB_mm2: 11.7; SizeArea_mm2: 5.6; SizeX_mm: 3.5; SizeY_mm: 1.6; SizeZ_mm: 1.1; AEC Category: Q101
D902 D903 = 150060YS75000: as D801 on sheet TIDA-01168_Control
R900 R920 = RC0603FR-07634RL: RES, 634, 1%, 0.1 W, 0603; Manufacturer: Yageo America; CompType: Resistor; Value: 634; Value_Code: 634R; Tolerance_%: 1; Power_W: 0.1; Value2: 0.1W; VDC_V: 150; TempCo: 200 ppm/C; EIA_Code: E96; U/M: EA; AEC Category: Q200; SizeArea_mm2: 1.28; SizeX_mm: 1.6; SizeY_mm: 0.8
R901 R904 R914 R915 = RC0603FR-0710RL: RES, 10.0, 1%, 0.1 W, 0603; Manufacturer: Yageo America; CompType: Resistor; Value: 10.0; Res_ohm: 10; Value_Code: 10R0; Tolerance_%: 1; Power_W: 0.1; Value2: 0.1W; VDC_V: 150; TempCo: 200 ppm/C; EIA_Code: E96; U/M: EA; AEC Category: Q200; SizeArea_mm2: 1.28; SizeX_mm: 1.6; SizeY_mm: 0.8
R902 R903 = RC0603FR-0795K3L: RES, 95.3 k, 1%, 0.1 W, 0603; Manufacturer: Yageo America; CompType: Resistor; Value: 95.3k; Res_ohm: 95300; Value_Code: 95k3; Tolerance_%: 1; Power_W: 0.1; Value2: 0.1W; VDC_V: 150; TempCo: 200 ppm/C; EIA_Code: E96; U/M: EA; AEC Category: Q200; SizeArea_mm2: 1.28; SizeX_mm: 1.6; SizeY_mm: 0.8
R905 R906 R908 R911 = RC0603FR-0710KL: as R808 on sheet TIDA-01168_Control
R907 R913 = RC0603FR-072RL: RES, 2.00, 1%, 0.1 W, 0603; Manufacturer: Yageo America; CompType: Resistor; Value: 2.00; Res_ohm: 2; Value_Code: 2R00; Tolerance_%: 1; Power_W: 0.1; Value2: 0.1W; VDC_V: 150; TempCo: 200 ppm/C; EIA_Code: E96; U/M: EA; AEC Category: Q200; SizeArea_mm2: 1.28; SizeX_mm: 1.6; SizeY_mm: 0.8
R909 R912 = RC0603FR-0740K2L: RES, 40.2 k, 1%, 0.1 W, 0603; Manufacturer: Yageo America; CompType: Resistor; Value: 40.2k; Res_ohm: 40200; Value_Code: 40k2; Tolerance_%: 1; Power_W: 0.1; Value2: 0.1W; VDC_V: 150; TempCo: 200 ppm/C; EIA_Code: E96; U/M: EA; AEC Category: Q200; SizeArea_mm2: 1.28; SizeX_mm: 1.6; SizeY_mm: 0.8
R910 = RC0603FR-0724RL: RES, 24.0, 1%, 0.1 W, 0603; Manufacturer: Yageo America; CompType: Resistor; Value: 24.0; Res_ohm: 24; Value_Code: 24R0; Tolerance_%: 1; Power_W: 0.1; Value2: 0.1W; VDC_V: 150; TempCo: 200 ppm/C; U/M: EA; AEC Category: Q200; SizeArea_mm2: 1.28; SizeX_mm: 1.6; SizeY_mm: 0.8
R916 R917 = RC0603FR-071K5L: as R802 on sheet TIDA-01168_Control
R918 R919 = RC0603FR-0764K9L: RES, 64.9 k, 1%, 0.1 W, 0603; Manufacturer: Yageo America; CompType: Resistor; Value: 64.9k; Res_ohm: 64900; Value_Code: 64k9; Tolerance_%: 1; Power_W: 0.1; Value2: 0.1W; VDC_V: 150; TempCo: 200 ppm/C; EIA_Code: E96; U/M: EA; AEC Category: Q200; SizeArea_mm2: 1.28; SizeX_mm: 1.6; SizeY_mm: 0.8
U900 = LM5170QPHPRQ1: Dual Channel 48V-12V Bidirectional Current Controller, PHP0048D; Alternate PartNumber: LM5170QPHPTQ1; Manufacturer: Texas Instruments; SymbolCreator: Altium; SizeArea_mm2: 81; SizeAreaWB_mm2: 121; SizeX_mm: 9; SizeZ_mm: 1.2; CompType: IC; U/M: EA

## Sheet TIDA-01168_BiasSupply.SchDoc: Bias Supplies
size 431 x 279 mm; Date: Not shown in title block; ApprovedBy: Not shown in title block; CheckedBy: Not shown in title block; Author: Not shown in title block; CompanyName: Not shown in title block; Engineer: Not shown in title block; Organization: Not shown in title block; Address1: Not shown in title block; Address2: Not shown in title block; Address3: Not shown in title block; Address4: Not shown in title block; DocumentNumber: 7; Revision: Use project parameter SCH_Rev; SheetNumber: 7; SheetTotal: 11; PageSetup: Record=PageOptions¦CenterHorizontal=True¦CenterVertical=True¦PrintScale=1.00¦XCorrection=1.00¦YCorrection=1.00¦PrintKind=0¦BorderSize=5000000¦LeftOffset=0¦BottomOffset=0¦Orientation=2¦PaperLength=1000¦PaperWidth=1000¦Scale=100¦PaperSource=15¦PrintQuality=600¦MediaType=1¦DitherType=10¦PaperKind=Letter¦PrintScaleMode=1
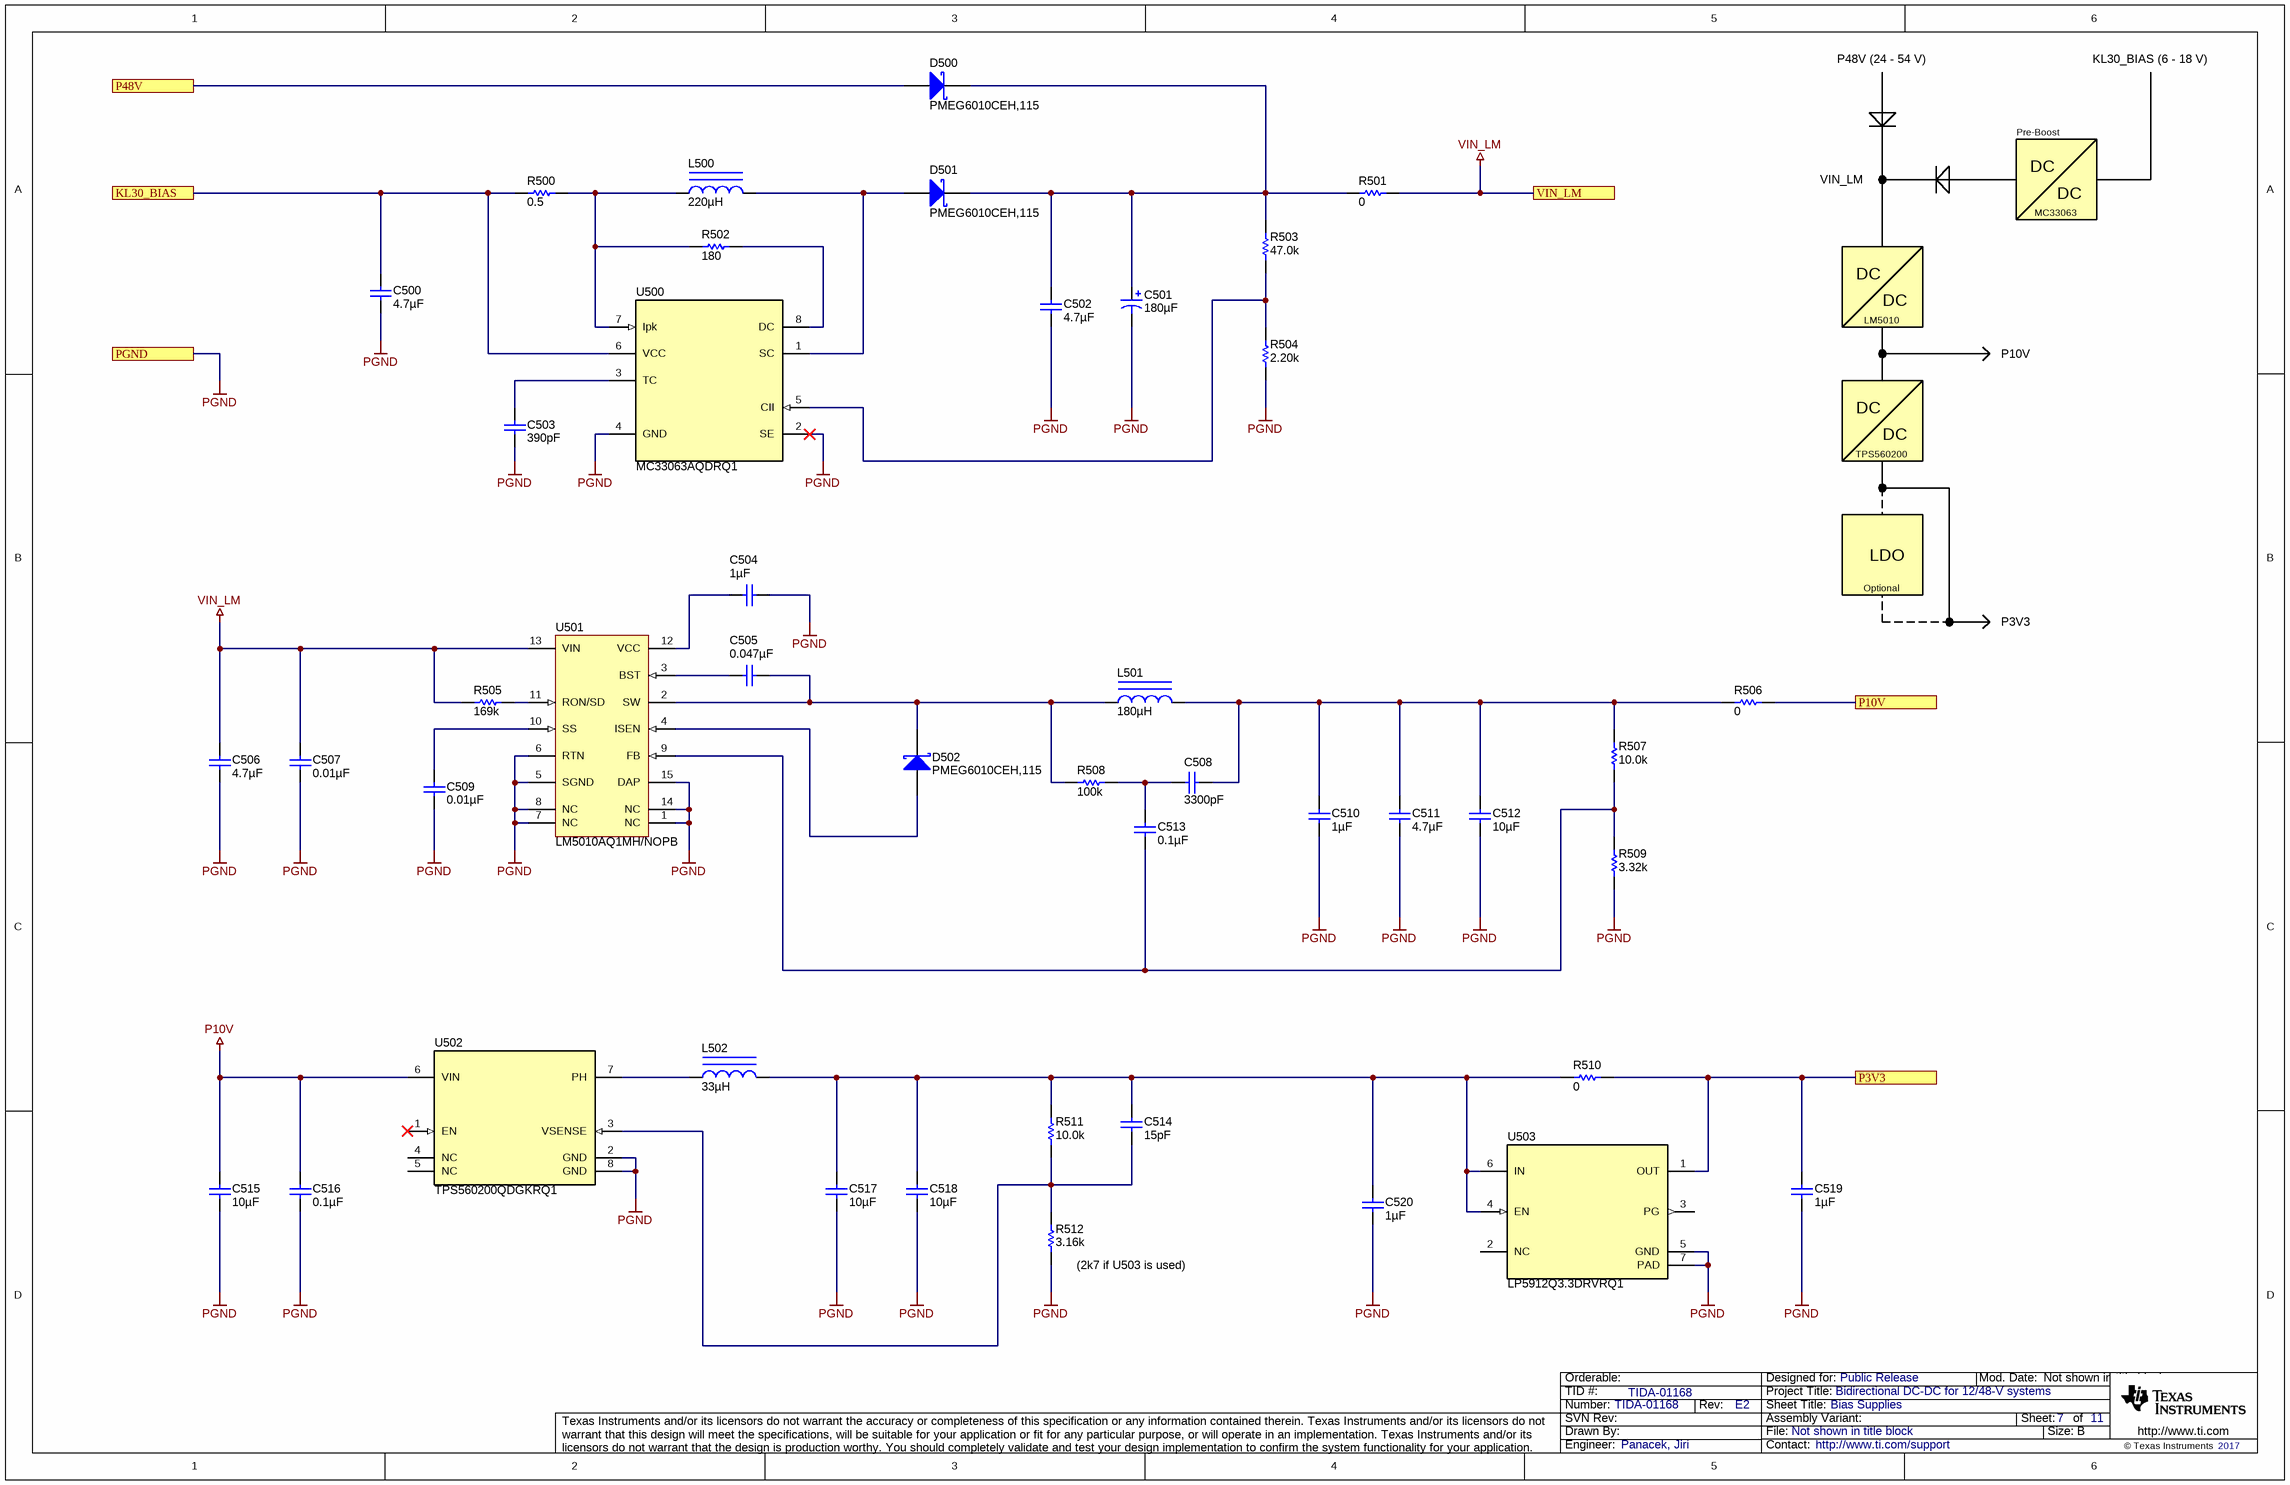
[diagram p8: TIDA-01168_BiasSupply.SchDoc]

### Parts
C500  ValueDisplayed: 4.7µF  [1210_220]  (hidden comment: CGA6M3X7S2A475K200AB)
C501  ValueDisplayed: 180µF  [UCZ_1250x1350]  (hidden comment: UCZ1J181MNQ1MS)
C502  ValueDisplayed: 4.7µF  [1210_220]  (hidden comment: CGA6M3X7S2A475K200AB)
C503  ValueDisplayed: 390pF  [0603]  (hidden comment: GRM1885C1H391JA01D)
C504  ValueDisplayed: 1µF  [0603]  (hidden comment: GCM188R71E105KA64D)
C505  ValueDisplayed: 0.047µF  [0603]  (hidden comment: GCM188R71E473KA37D)
C506  ValueDisplayed: 4.7µF  [1210_220]  (hidden comment: CGA6M3X7S2A475K200AB)
C507  ValueDisplayed: 0.01µF  [0805_HV]  (hidden comment: GRM21BR72A103KA01L)
C508  ValueDisplayed: 3300pF  [0603]  (hidden comment: GCM188R72A332KA37D)
C509  ValueDisplayed: 0.01µF  [0603]  (hidden comment: GCM188R71H103KA37D)
C510  ValueDisplayed: 1µF  [0603]  (hidden comment: GCM188R71E105KA64D)
C511  ValueDisplayed: 4.7µF  [0805_HV]  (hidden comment: GCM21BR71C475KA73K)
C512  ValueDisplayed: 10µF  [0805_HV]  (hidden comment: GCM21BC71C106KE36L)
C513  ValueDisplayed: 0.1µF  [0603]  (hidden comment: GCM188R71H104KA57D)
C514  ValueDisplayed: 15pF  [0603]  (hidden comment: GCM1885C1H150JA16D)
C515  ValueDisplayed: 10µF  [0805_HV]  (hidden comment: GCM21BC71C106KE36L)
C516  ValueDisplayed: 0.1µF  [0603]  (hidden comment: GCM188R71H104KA57D)
C517  ValueDisplayed: 10µF  [0805_HV]  (hidden comment: GCM21BC71C106KE36L)
C518  ValueDisplayed: 10µF  [0805_HV]  (hidden comment: GCM21BC71C106KE36L)
C519  ValueDisplayed: 1µF  [0603]  (hidden comment: GCM188R71E105KA64D)
C520  ValueDisplayed: 1µF  [0603]  (hidden comment: GCM188R71E105KA64D)
D500  PMEG6010CEH,115  [SOD-123F]
D501  PMEG6010CEH,115  [SOD-123F]
D502  PMEG6010CEH,115  [SOD-123F]
L500  ValueDisplayed: 220µH  [MSS7341]  (hidden comment: MSS7341T-224MLB)
L501  ValueDisplayed: 180µH  [MSS1048]  (hidden comment: MSS1048-184KLB)
L502  ValueDisplayed: 33µH  [MSS5121]  (hidden comment: MSS5121-333MLB)
R500  ValueDisplayed: 0.5  [1206]  (hidden comment: CSR1206FKR500)
R501  ValueDisplayed: 0  [5106]  (hidden comment: 5106)
R502  ValueDisplayed: 180  [0603]  (hidden comment: CRCW0603180RJNEA)
R503  ValueDisplayed: 47.0k  [0603]  (hidden comment: RC0603FR-0747KL)
R504  ValueDisplayed: 2.20k  [0603]  (hidden comment: RC0603FR-072K2L)
R505  ValueDisplayed: 169k  [0603]  (hidden comment: RC0603FR-07169KL)
R506  ValueDisplayed: 0  [5106]  (hidden comment: 5106)
R507  ValueDisplayed: 10.0k  [0603]  (hidden comment: RC0603FR-0710KL)
R508  ValueDisplayed: 100k  [0603]  (hidden comment: RC0603FR-07100KL)
R509  ValueDisplayed: 3.32k  [0603]  (hidden comment: RC0603FR-073K32L)
R510  ValueDisplayed: 0  [5106]  (hidden comment: 5106)
R511  ValueDisplayed: 10.0k  [0603]  (hidden comment: RC0603FR-0710KL)
R512  ValueDisplayed: 3.16k  [0603]  (hidden comment: RC0603FR-073K16L)
U500  MC33063AQDRQ1  [D0008A_N]
U501  LM5010AQ1MH/NOPB  [MXA14A_N]
U502  TPS560200QDGKRQ1  [DGK0008A_M]
U503  LP5912Q3.3DRVRQ1  [DRV0006A]

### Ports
KL30_BIAS, P3V3, P10V, P48V, PGND, VIN_LM

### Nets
KL30_BIAS: C500.1 R500.2 U500.6(VCC) ; port KL30_BIAS
P3V3: C519.1 R510.2 U503.1(OUT) ; port P3V3
P10V: C515.1 C516.2 R506.2 U502.6(VIN) ; port P10V
P48V: D500.2(A) ; port P48V
PGND: C500.2 C501.2(-) C502.2 C503.2 C504.2 C506.2 C507.2 C509.2 C510.2 C511.2 C512.2 C515.2 C516.1 C517.2 C518.2 C519.2 C520.2 R504.1 R509.2 R512.2 U500.2(SE) U500.4(GND) U501.1(NC) U501.5(SGND) U501.6(RTN) U501.7(NC) U501.8(NC) U501.14(NC) U501.15(DAP) U502.2(GND) U502.8(GND) U503.5(GND) U503.7(PAD) ; port PGND  [project net GND]
VIN_LM: C506.1 C507.1 R501.2 R505.1 U501.13(VIN) ; port VIN_LM
NetC501_1: C501.1(+) C502.1 D500.1(K) D501.1(K) R501.1 R503.2
NetC503_1: C503.1 U500.3(TC)
NetC504_1: C504.1 U501.12(VCC)
NetC505_1: C505.1 U501.3(BST)
NetC505_2: C505.2 D502.1(K) L501.1 R508.1 U501.2(SW)
NetC508_1: C508.1 C510.1 C511.1 C512.1 L501.2 R506.1 R507.1
NetC508_2: C508.2 C513.2 R508.2
NetC509_1: C509.1 U501.10(SS)
NetC513_1: C513.1 R507.2 R509.1 U501.9(FB)
NetC514_1: C514.1 C517.1 C518.1 C520.1 L502.2 R510.1 R511.1 U503.4(EN) U503.6(IN)
NetC514_2: C514.2 R511.2 R512.1 U502.3(VSENSE)
NetD501_2: D501.2(A) L500.2 U500.1(SC)
NetD502_2: D502.2(A) U501.4(ISEN)
NetL500_1: L500.1 R500.1 R502.1 U500.7(Ipk)
NetL502_1: L502.1 U502.7(PH)
NetR502_2: R502.2 U500.8(DC)
NetR503_1: R503.1 R504.2 U500.5(CII)
NetR505_2: R505.2 U501.11(RON/SD)

Not connected (* = marked no-connect by the designer): U502 1(EN)* 4(NC) 5(NC); U503 2(NC) 3(PG)

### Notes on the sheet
- P48V (24 - 54 V)
- KL30_BIAS (6 - 18 V)
- Pre-Boost
- DC
- VIN_LM
- MC33063
- LM5010
- P10V
- TPS560200
- LDO
- Optional
- P3V3
- (near R512) (2k7 if U503 is used)

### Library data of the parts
C500 C502 C506 = CGA6M3X7S2A475K200AB: CAP, CERM, 4.7 µF, 100 V, +/- 10%, X7S, AEC-Q200 Grade 1, 1210; Manufacturer: TDK; Polarized: N; CompType: Capacitor; Value: 4.7uF; U/M: EA; Cap_F: 0.0000047; Tolerance_%: 10; ESR_ohm: 0.004236; Value1: 0.004236 ohm; VDC_V: 100; Value2: 100V; IRMS_A: 3.57337; TaMin_C: -55; TaMax_C: 125; SizeArea_mm2: 8; SizeAreaWB_mm2: 14.7; SizeX_mm: 3.2; SizeY_mm: 2.5; SizeZ_mm: 2.2; AEC Category: Q200; AEC Qualified: Y; AEC Grade: 1
C501 = UCZ1J181MNQ1MS: CAP, AL, 180 µF, 63 V, +/- 20%, 0.2 ohm, AEC-Q200 Grade 1, SMD; Manufacturer: Nichicon; Polarized: Y; CompType: Capacitor; Value: 180uF; U/M: EA; Cap_F: 0.00018; Tolerance_%: 20; Value1: 0.2 ohm; VDC_V: 63; Value2: 63V; ESR_ohm: 0.2; IRMS_A: 1; TaMin_C: -40; TaMax_C: 125; Cap_Case: 12.5x13.5mm; AEC Category: Q200
C503 = GRM1885C1H391JA01D: CAP, CERM, 390 pF, 50 V, +/- 5%, C0G/NP0, 0603; Manufacturer: MuRata; Polarized: N; CompType: Capacitor; Value: 390pF; U/M: EA; Cap_F: 0.00000000039; Tolerance_%: 5; Value1: Unknown; VDC_V: 50; Value2: 50V; TaMin_C: -55; TaMax_C: 125; SizeArea_mm2: 1.28; SizeAreaWB_mm2: 4.68; SizeX_mm: 1.6; SizeY_mm: 0.8; SizeZ_mm: 1; AEC Category: Q200
C504 C510 C519 C520 = GCM188R71E105KA64D: as C801 on sheet TIDA-01168_Control
C505 = GCM188R71E473KA37D: as C903 on sheet TIDA-01168_LM5170_Subsystem
C507 = GRM21BR72A103KA01L: CAP, CERM, 0.01 µF, 100 V, +/- 10%, X7R, 0805; Manufacturer: MuRata; Polarized: N; CompType: Capacitor; Value: 0.01uF; U/M: EA; Cap_F: 0.00000001; Tolerance_%: 10; Value1: Unknown; VDC_V: 100; Value2: 100V; TaMin_C: -55; TaMax_C: 125; Cap_Case: 0805; AEC Category: Q200; SizeArea_mm2: 2.5; SizeAreaWB_mm2: 6.75; SizeX_mm: 2; SizeY_mm: 1.25; SizeZ_mm: 1.45
C508 = GCM188R72A332KA37D: as C912 on sheet TIDA-01168_LM5170_Subsystem
C509 = GCM188R71H103KA37D: as C800 on sheet TIDA-01168_Control
C511 = GCM21BR71C475KA73K: as C910 on sheet TIDA-01168_LM5170_Subsystem
C512 C515 C517 C518 = GCM21BC71C106KE36L: CAP, CERM, 10 µF, 16 V, +/- 10%, X7S, AEC-Q200 Grade 1, 0805; Manufacturer: MuRata; Polarized: N; CompType: Capacitor; Value: 10uF; U/M: EA; Cap_F: 0.00001; Tolerance_%: 10; Value1: Unknown; VDC_V: 16; Value2: 16V; TaMin_C: -55; TaMax_C: 125; Cap_Case: 0805; AEC Category: Q200; AEC Qualified: Y; AEC Grade: 1; SizeArea_mm2: 2.5; SizeAreaWB_mm2: 6.75; SizeX_mm: 2; SizeY_mm: 1.25; SizeZ_mm: 1.45
C513 C516 = GCM188R71H104KA57D: as C805 on sheet TIDA-01168_Control
C514 = GCM1885C1H150JA16D: CAP, CERM, 15 pF, 50 V, +/- 5%, C0G/NP0, AEC-Q200 Grade 1, 0603; Manufacturer: MuRata; Polarized: N; CompType: Capacitor; Value: 15pF; U/M: EA; Cap_F: 0.000000000015; Tolerance_%: 5; Value1: Unknown; VDC_V: 50; Value2: 50V; TaMin_C: -55; TaMax_C: 125; SizeArea_mm2: 1.28; SizeAreaWB_mm2: 4.68; SizeX_mm: 1.6; SizeY_mm: 0.8; SizeZ_mm: 1; AEC Category: Q200; AEC Qualified: Y
D500-D502 = PMEG6010CEH,115: as D900 on sheet TIDA-01168_LM5170_Subsystem
L500 = MSS7341T-224MLB: Inductor, Shielded Drum Core, Ferrite, 220 µH, 0.51 A, 0.65 ohm, AEC-Q200 Grade 1, SMD; Manufacturer: Coilcraft; Value: 220uH; Ind_H: 220.0E-6; Imax_A: 0.51; Irms: 0.78A @ 40C rise; Isat: 0.51A @ 30% inductance drop; DCR_ohm: 0.65; Value2: 0.51A; AEC Category: Q200; AEC Qualified: Y; AEC Grade: 1
L501 = MSS1048-184KLB: Inductor, Shielded Drum Core, Ferrite, 180 µH, 1.02 A, 0.45 ohm, SMD; Manufacturer: Coilcraft; Value: 180uH; Ind_H: 180.0E-6; Imax_A: 1.02; Irms: 1.24A @ 40C rise; Isat: 1.02A @ 30% inductance drop; DCR_ohm: 0.45; Value2: 1.02A; AEC Category: Q200
L502 = MSS5121-333MLB: Inductor, Shielded Drum Core, Ferrite, 33 µH, 0.67 A, 0.48 ohm, SMD; Manufacturer: Coilcraft; Value: 33uH; Ind_H: 33.0E-6; Imax_A: 0.67; Irms: 0.76A @ 40C rise; Isat: 0.67A @ 30% inductance drop; DCR_ohm: 0.48; Value2: 0.67A; AEC Category: Q200
R500 = CSR1206FKR500: RES, 0.5, 1%, 0.5 W, 1206; Manufacturer: Stackpole Electronics Inc; CompType: Resistor; Value: 0.5; Value_Code: R500; Tolerance_%: 1; Value2: 0.5W; TempCo: 100 ppm/C; U/M: EA; AEC Category: Q200; SizeArea_mm2: 5.12; SizeX_mm: 3.2; SizeY_mm: 1.6; SizeZ_mm: 1.35
R501 R506 R510 = 5106: RES, 0, 1%, 0.5 W, 0805; Manufacturer: Keystone; CompType: Resistor; Value: 0; Tolerance_%: 1; Power_W: 0.5; Value2: 0.5W; TempCo: ppm/C; SizeArea_mm2: 2.5; SizeX_mm: 2; SizeY_mm: 1.25; SizeZ_mm: 0.84; U/M: EA; AEC Category: Q200; AEC Qualified: N
R502 = CRCW0603180RJNEA: RES, 180, 5%, 0.1 W, 0603; Manufacturer: Vishay-Dale; CompType: Resistor; Value: 180; Value_Code: 180R; Tolerance_%: 5; Power_W: 0.1; Value2: 0.1W; VDC_V: 75; TempCo: 200 ppm/C; EIA_Code: E24; U/M: EA; AEC Category: Q200; SizeArea_mm2: 1.28; SizeX_mm: 1.6; SizeY_mm: 0.8; SizeZ_mm: 1
R503 = RC0603FR-0747KL: RES, 47.0 k, 1%, 0.1 W, 0603; Manufacturer: Yageo America; CompType: Resistor; Value: 47.0k; Res_ohm: 47000; Value_Code: 47k0; Tolerance_%: 1; Power_W: 0.1; Value2: 0.1W; VDC_V: 150; TempCo: 200 ppm/C; U/M: EA; AEC Category: Q200; SizeArea_mm2: 1.28; SizeX_mm: 1.6; SizeY_mm: 0.8
R504 = RC0603FR-072K2L: RES, 2.20 k, 1%, 0.1 W, 0603; Manufacturer: Yageo America; CompType: Resistor; Value: 2.20k; Res_ohm: 2200; Value_Code: 2k20; Tolerance_%: 1; Power_W: 0.1; Value2: 0.1W; VDC_V: 150; TempCo: 200 ppm/C; U/M: EA; AEC Category: Q200; SizeArea_mm2: 1.28; SizeX_mm: 1.6; SizeY_mm: 0.8
R505 = RC0603FR-07169KL: RES, 169 k, 1%, 0.1 W, 0603; Manufacturer: Yageo America; CompType: Resistor; Value: 169k; Res_ohm: 169000; Tolerance_%: 1; Power_W: 0.1; Value2: 0.1W; VDC_V: 150; TempCo: 200 ppm/C; EIA_Code: E96; U/M: EA; AEC Category: Q200; SizeArea_mm2: 1.28; SizeX_mm: 1.6; SizeY_mm: 0.8
R507 R511 = RC0603FR-0710KL: as R808 on sheet TIDA-01168_Control
R508 = RC0603FR-07100KL: RES, 100 k, 1%, 0.1 W, 0603; Manufacturer: Yageo America; CompType: Resistor; Value: 100k; Res_ohm: 100000; Tolerance_%: 1; Power_W: 0.1; Value2: 0.1W; VDC_V: 150; TempCo: 200 ppm/C; EIA_Code: E96; U/M: EA; AEC Category: Q200; SizeArea_mm2: 1.28; SizeX_mm: 1.6; SizeY_mm: 0.8
R509 = RC0603FR-073K32L: RES, 3.32 k, 1%, 0.1 W, 0603; Manufacturer: Yageo America; CompType: Resistor; Value: 3.32k; Res_ohm: 3320; Value_Code: 3k32; Tolerance_%: 1; Power_W: 0.1; Value2: 0.1W; VDC_V: 150; TempCo: 200 ppm/C; EIA_Code: E96; U/M: EA; AEC Category: Q200; SizeArea_mm2: 1.28; SizeX_mm: 1.6; SizeY_mm: 0.8
R512 = RC0603FR-073K16L: RES, 3.16 k, 1%, 0.1 W, 0603; Manufacturer: Yageo America; CompType: Resistor; Value: 3.16k; Res_ohm: 3160; Value_Code: 3k16; Tolerance_%: 1; Power_W: 0.1; Value2: 0.1W; VDC_V: 150; TempCo: 200 ppm/C; EIA_Code: E96; U/M: EA; AEC Category: Q200; SizeArea_mm2: 1.28; SizeX_mm: 1.6; SizeY_mm: 0.8
U500 = MC33063AQDRQ1: 1.5-A PEAK BOOST / BUCK / INVERTING SWITCHING REGULATOR, D0008A; Manufacturer: Texas Instruments; SymbolCreator: Altium; SizeArea_mm2: 30.38; SizeAreaWB_mm2: 56.58; SizeX_mm: 4.9; SizeY_mm: 6.2; SizeZ_mm: 1.75; CompType: IC; U/M: EA
U501 = LM5010AQ1MH/NOPB: High Voltage 1A Step Down Switching Regulator, 14-pin TSSOP-EP, Pb-Free; Manufacturer: Texas Instruments; PackageTopMarking: NSUZXYTT*L5010A*Q1MH; PowerWise: N; CompType: Switcher
U502 = TPS560200QDGKRQ1: 4.5V to 18V Input, 500mA Synchronous Step Down SWIFT Converter with Advanced Eco-mode, DGK0008A; Alternate PartNumber: TPS560200QDGKTQ1; Manufacturer: Texas Instruments; SymbolCreator: a0411947; SizeArea_mm2: 15.655; SizeAreaWB_mm2: 35.955; SizeX_mm: 5.05; SizeY_mm: 3.1; SizeZ_mm: 1.1; CompType: IC; U/M: EA
U503 = LP5912Q3.3DRVRQ1: Ultra Low-Noise, 500-mA Linear Regulator for RF and Analog Circuits - Requires No Bypass Capacitor, DRV0006A; Alternate PartNumber: LP5912Q3.3DRVTQ1; Manufacturer: Texas Instruments; SymbolCreator: a0411947; SizeArea_mm2: 4; SizeAreaWB_mm2: 9; SizeX_mm: 2; SizeZ_mm: 0.8; CompType: IC; U/M: EA

## Sheet TIDA-01168_If.SchDoc: System Interface
size 431 x 279 mm; Date: Not shown in title block; ApprovedBy: Not shown in title block; CheckedBy: Not shown in title block; Author: Not shown in title block; CompanyName: Not shown in title block; Engineer: Not shown in title block; Organization: Not shown in title block; Address1: Not shown in title block; Address2: Not shown in title block; Address3: Not shown in title block; Address4: Not shown in title block; DocumentNumber: 10; Revision: Use project parameter SCH_Rev; SheetNumber: 10; SheetTotal: 11; PageSetup: Record=PageOptions¦CenterHorizontal=True¦CenterVertical=True¦PrintScale=1.00¦XCorrection=1.00¦YCorrection=1.00¦PrintKind=0¦BorderSize=5000000¦LeftOffset=0¦BottomOffset=0¦Orientation=2¦PaperLength=1000¦PaperWidth=1000¦Scale=100¦PaperSource=15¦PrintQuality=600¦MediaType=1¦DitherType=10¦PaperKind=Letter¦PrintScaleMode=1
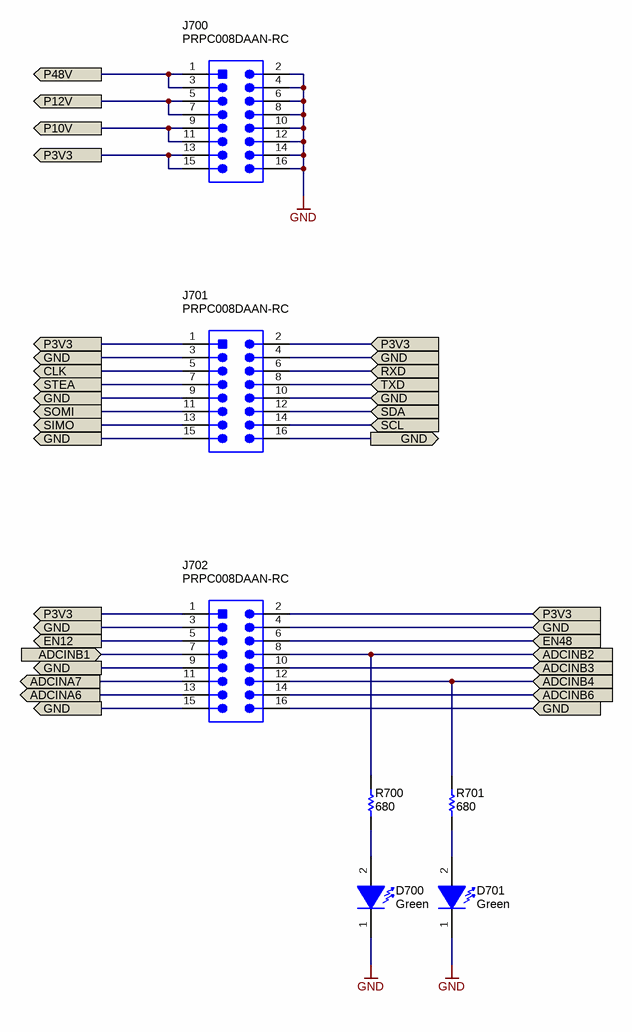
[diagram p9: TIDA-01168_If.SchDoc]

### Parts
D700  value Green  [WL-SMCW_GREEN]  (hidden comment: 150060GS75000)
D701  value Green  [WL-SMCW_GREEN]  (hidden comment: 150060GS75000)
J700  PRPC008DAAN-RC  [Sullins_xxxC008DAAN]
J701  PRPC008DAAN-RC  [Sullins_xxxC008DAAN]
J702  PRPC008DAAN-RC  [Sullins_xxxC008DAAN]
R700  ValueDisplayed: 680  [0603]  (hidden comment: RC0603FR-07680RL)
R701  ValueDisplayed: 680  [0603]  (hidden comment: RC0603FR-07680RL)

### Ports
ADCINA6, ADCINA7, ADCINB1, ADCINB2, ADCINB3, ADCINB4, ADCINB6, CLK, EN12, EN48, GND, P3V3, P10V, P12V, P48V, RXD, SCL, SDA, SIMO, SOMI, STEA, TXD

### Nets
CS1B_A: J700.5 J700.7 ; port P12V
GND: D700.1(K) D701.1(K) J700.2 J700.4 J700.6 J700.8 J700.10 J700.12 J700.14 J700.16 J701.3 J701.4 J701.9 J701.10 J701.15 J701.16 J702.3 J702.4 J702.9 J702.15 J702.16 ; port GND
P3V3: J700.13 J700.15 J701.1 J701.2 J702.1 J702.2 ; port P3V3
P10V: J700.9 J700.11 ; port P10V
P48V: J700.1 J700.3 ; port P48V
ADCINA6: J702.13 ; port ADCINA6
ADCINA7: J702.11 ; port ADCINA7
ADCINB1: J702.7 ; port ADCINB1
ADCINB2: J702.8 R700.1 ; port ADCINB2
ADCINB3: J702.10 ; port ADCINB3
ADCINB4: J702.12 R701.1 ; port ADCINB4
ADCINB6: J702.14 ; port ADCINB6
CLK: J701.5 ; port CLK
EN12: J702.5 ; port EN12
EN48: J702.6 ; port EN48
RXD: J701.6 ; port RXD
SCL: J701.14 ; port SCL
SDA: J701.12 ; port SDA
SIMO: J701.13 ; port SIMO
SOMI: J701.11 ; port SOMI
STEA: J701.7 ; port STEA
TXD: J701.8 ; port TXD
NetD700_2: D700.2(A) R700.2
NetD701_2: D701.2(A) R701.2

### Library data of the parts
D700 D701 = 150060GS75000: as D800 on sheet TIDA-01168_Control
J700-J702 = PRPC008DAAN-RC: Header, 2.54mm, 8x2, Gold, TH; Manufacturer: Sullins Connector Solutions; SymbolCreator: a0412235; U/M: EA
R700 R701 = RC0603FR-07680RL: as R801 on sheet TIDA-01168_Control

## Sheet TIDA-01168_48V_Flt.SchDoc: 48-V Filter
size 431 x 279 mm; Date: Not shown in title block; ApprovedBy: Not shown in title block; CheckedBy: Not shown in title block; Author: Not shown in title block; CompanyName: Not shown in title block; Engineer: Not shown in title block; Organization: Not shown in title block; Address1: Not shown in title block; Address2: Not shown in title block; Address3: Not shown in title block; Address4: Not shown in title block; DocumentNumber: 3; Revision: Use project parameter SCH_Rev; SheetNumber: 3; SheetTotal: 11; PageSetup: Record=PageOptions¦CenterHorizontal=True¦CenterVertical=True¦PrintScale=1.00¦XCorrection=1.00¦YCorrection=1.00¦PrintKind=0¦BorderSize=5000000¦LeftOffset=0¦BottomOffset=0¦Orientation=2¦PaperLength=1000¦PaperWidth=1000¦Scale=100¦PaperSource=15¦PrintQuality=600¦MediaType=1¦DitherType=10¦PaperKind=Letter¦PrintScaleMode=1
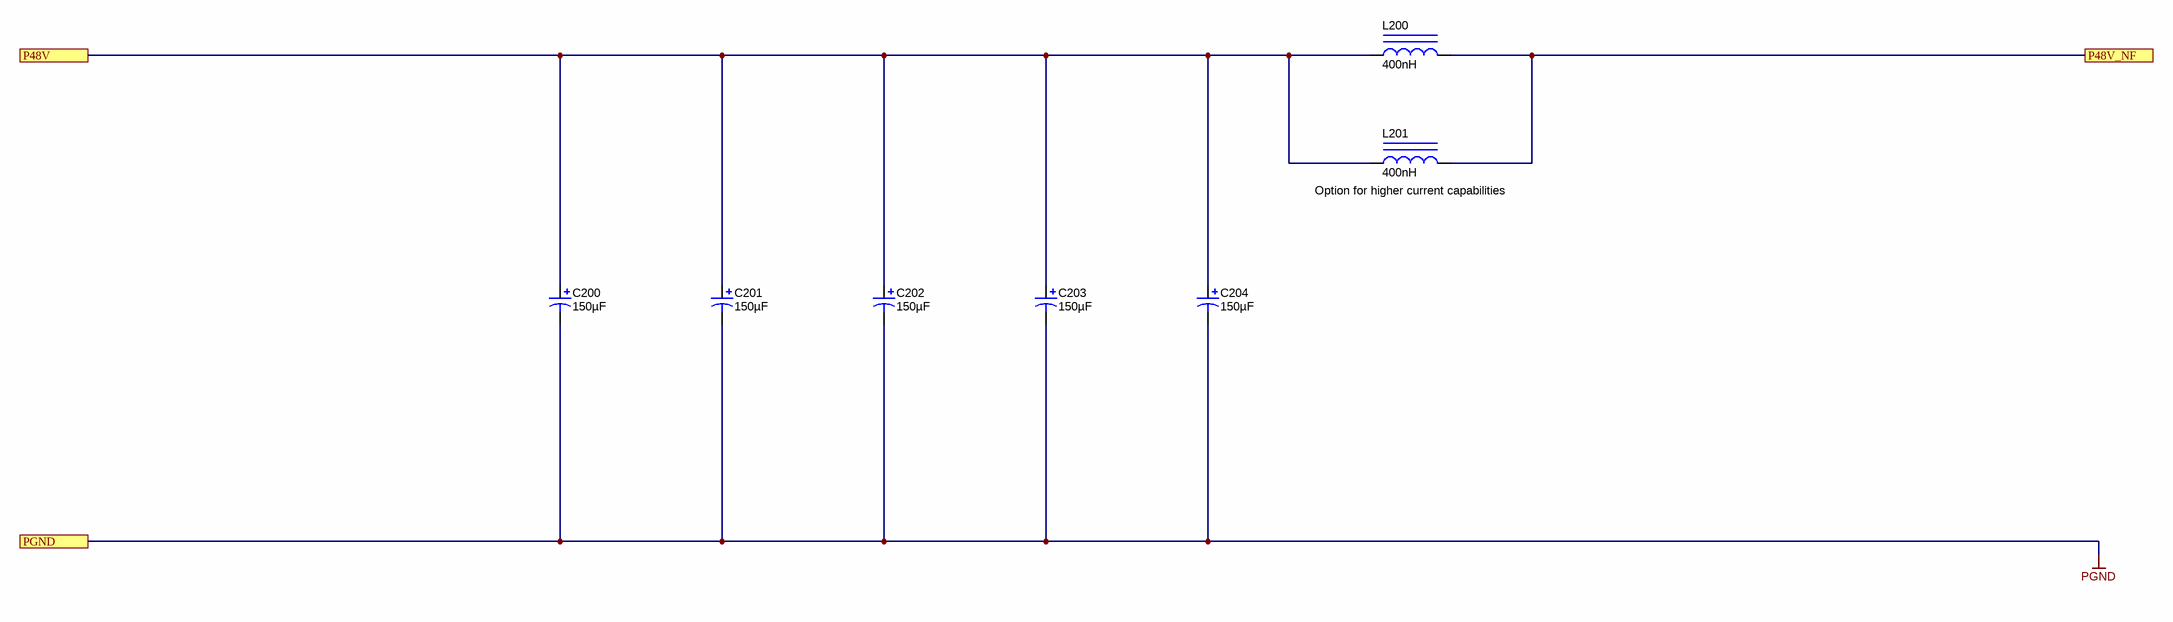
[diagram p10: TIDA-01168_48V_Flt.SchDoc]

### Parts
C200  ValueDisplayed: 150µF  [UCZ_1250x1350]  (hidden comment: UCZ1K151MNQ1MS)
C201  ValueDisplayed: 150µF  [UCZ_1250x1350]  (hidden comment: UCZ1K151MNQ1MS)
C202  ValueDisplayed: 150µF  [UCZ_1250x1350]  (hidden comment: UCZ1K151MNQ1MS)
C203  ValueDisplayed: 150µF  [UCZ_1250x1350]  (hidden comment: UCZ1K151MNQ1MS)
C204  ValueDisplayed: 150µF  [UCZ_1250x1350]  (hidden comment: UCZ1K151MNQ1MS)
L200  ValueDisplayed: 400nH  [XAL1060]  (hidden comment: XAL1060-401MEB)
L201  ValueDisplayed: 400nH  [XAL1060]  (hidden comment: XAL1060-401MEB)

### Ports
P48V, P48V_NF, PGND

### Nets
P48V: C200.1(+) C201.1(+) C202.1(+) C203.1(+) C204.1(+) L200.1 L201.1 ; port P48V
PGND: C200.2(-) C201.2(-) C202.2(-) C203.2(-) C204.2(-) ; port PGND  [project net GND]
P48V_NF: L200.2 L201.2 ; port P48V_NF

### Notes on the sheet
- (near L201) Option for higher current capabilities

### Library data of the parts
C200-C204 = UCZ1K151MNQ1MS: CAP, AL, 150 µF, 80 V, +/- 20%, 0.2 ohm, AEC-Q200 Grade 1, SMD; Manufacturer: Nichicon; Polarized: Y; CompType: Capacitor; Value: 150uF; U/M: EA; Cap_F: 0.00015; Tolerance_%: 20; Value1: 0.2 ohm; VDC_V: 80; Value2: 80V; ESR_ohm: 0.2; IRMS_A: 0.7; TaMin_C: -40; TaMax_C: 125; Cap_Case: 12.5x13.5mm; AEC Category: Q200; AEC Grade: 1
L200 L201 = XAL1060-401MEB: Inductor, Shielded, Composite, 400 nH, 36.8 A, 0.0008 ohm, AEC-Q200 Grade 1, SMD; Manufacturer: Coilcraft; Value: 400nH; Ind_H: 400.0E-9; Imax_A: 36.8; Irms: 36.8A @ 40C rise; Isat: 82A @ 30% inductance drop; DCR_ohm: 0.0008; Value2: 36.8A; AEC Category: Q200; AEC Qualified: Y; AEC Grade: 1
